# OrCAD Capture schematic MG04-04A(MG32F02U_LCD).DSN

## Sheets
1 01. Power Supply: size E; title: System Power; rev: 1.1; company: megawin; note: MG04-04
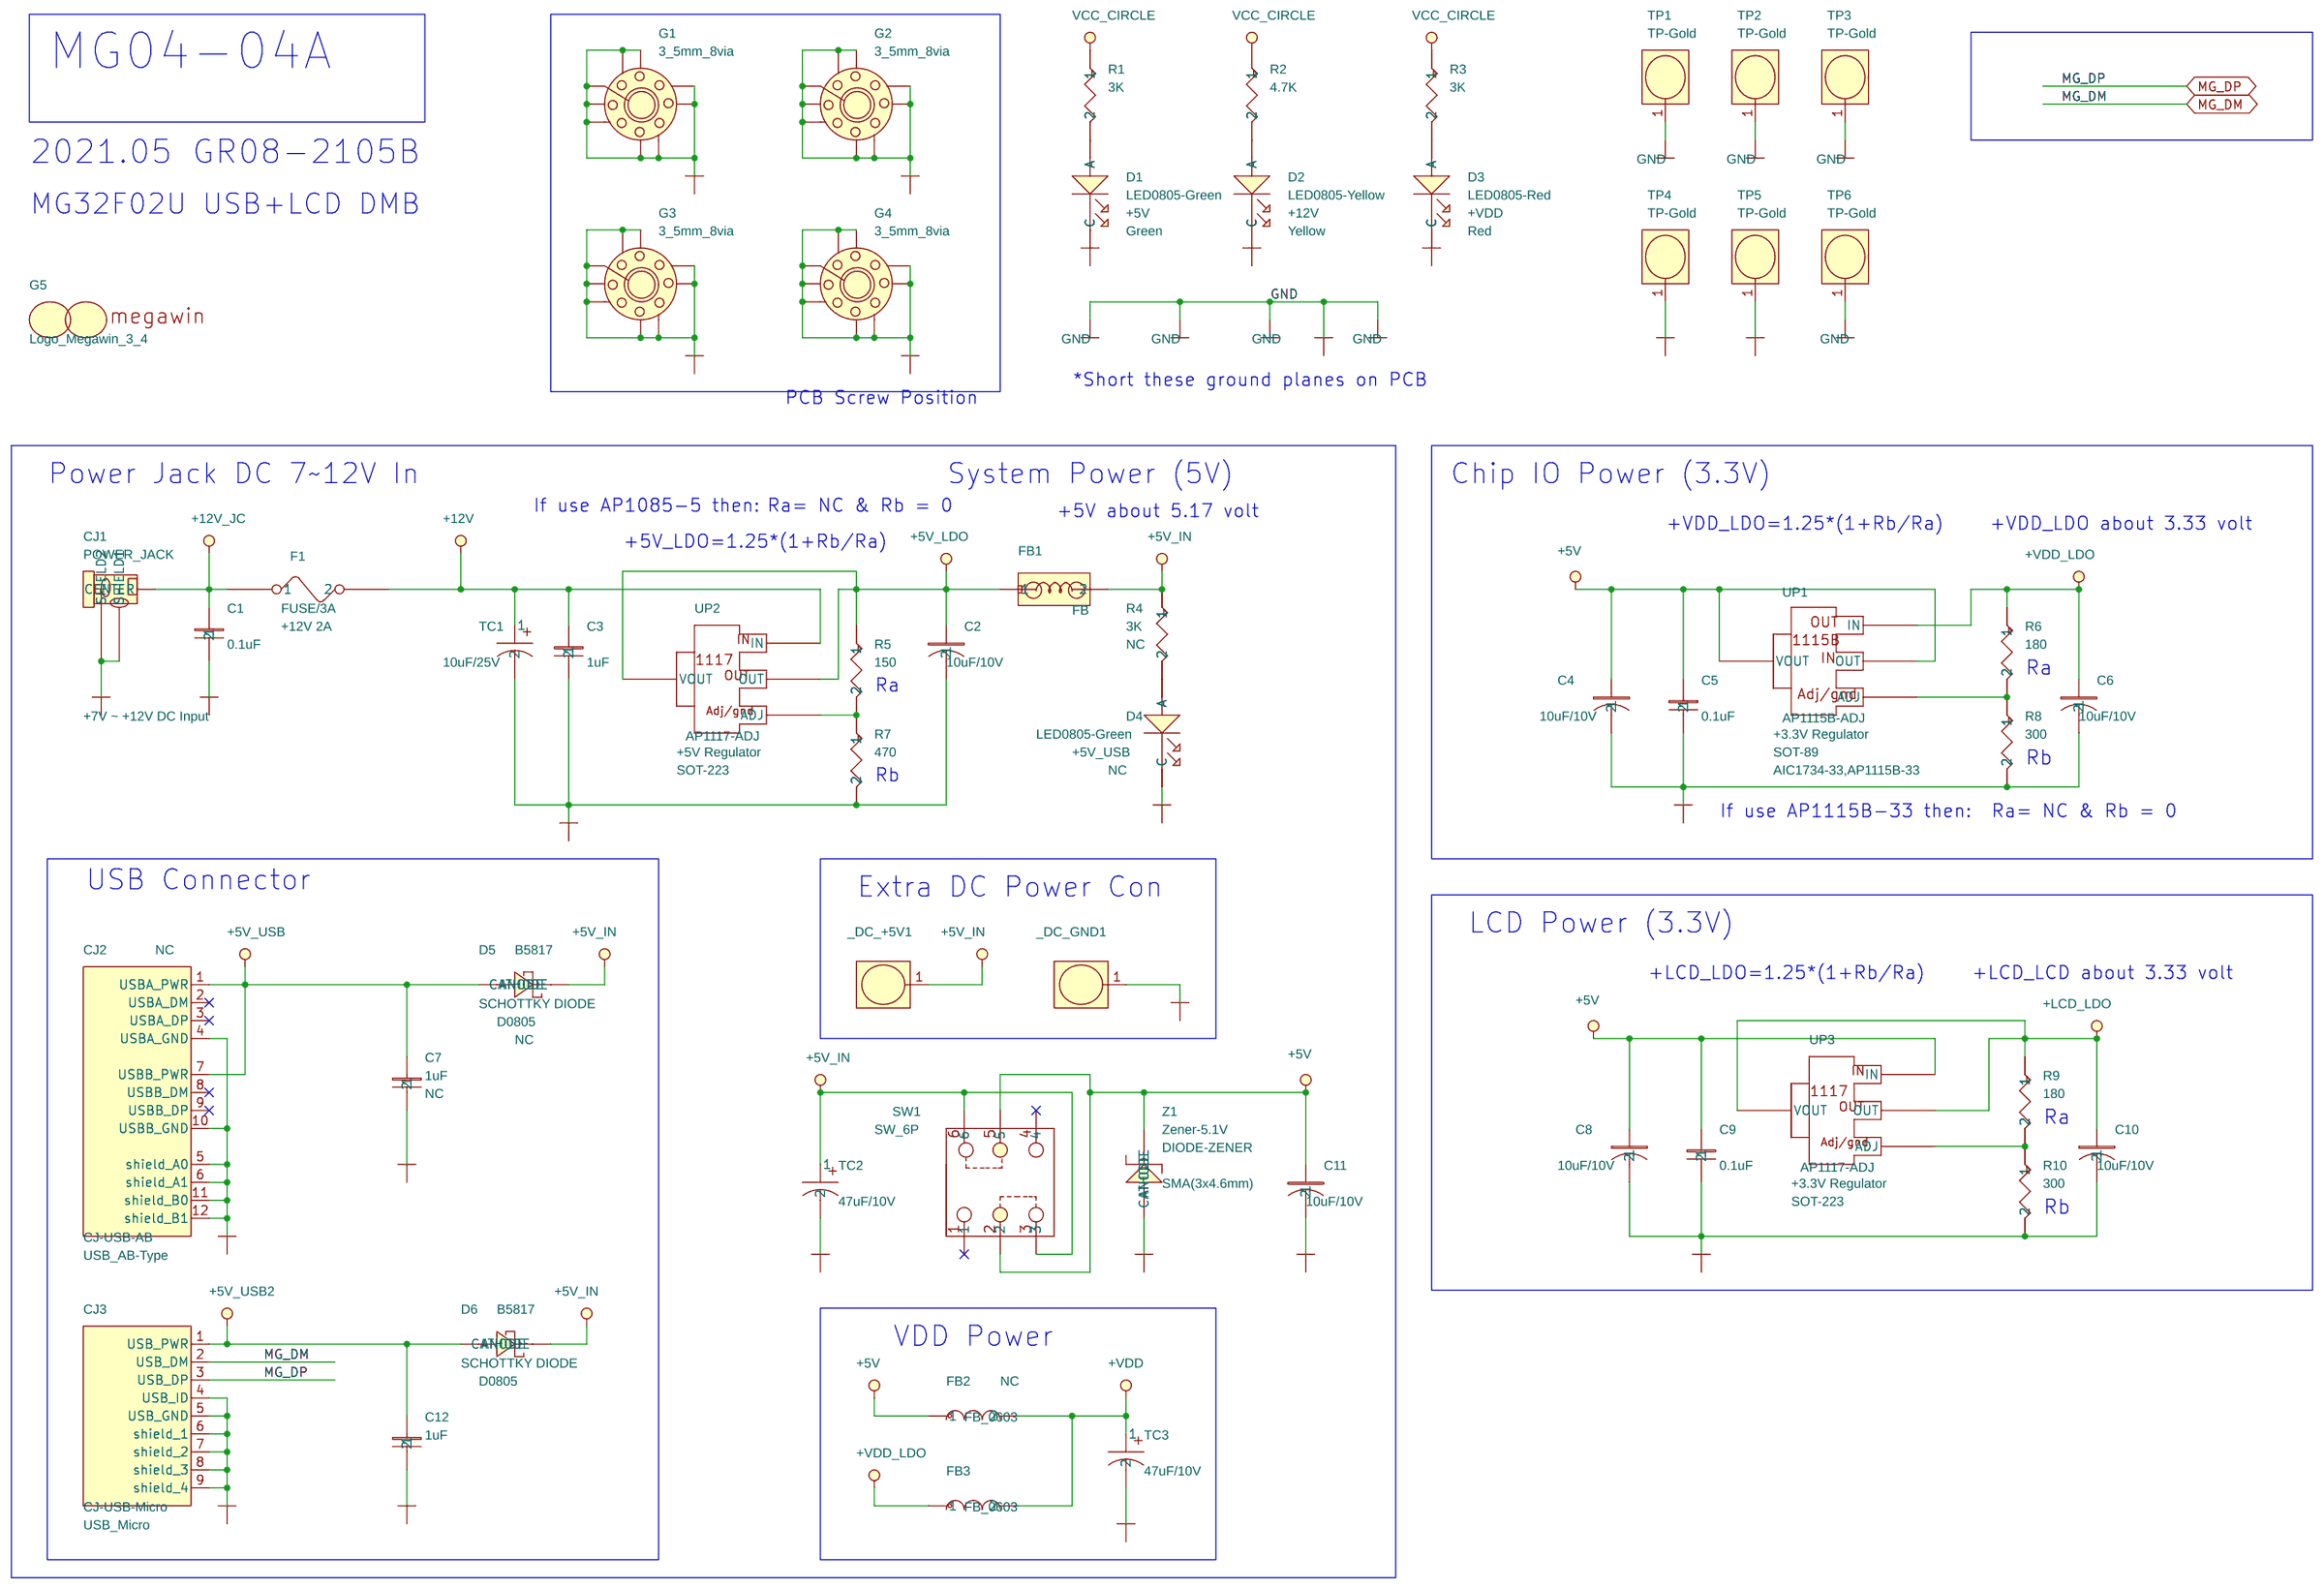
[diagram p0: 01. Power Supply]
2 02. MG32F02U_Main: size C; title: MG32F02U Chip; rev: 1.0
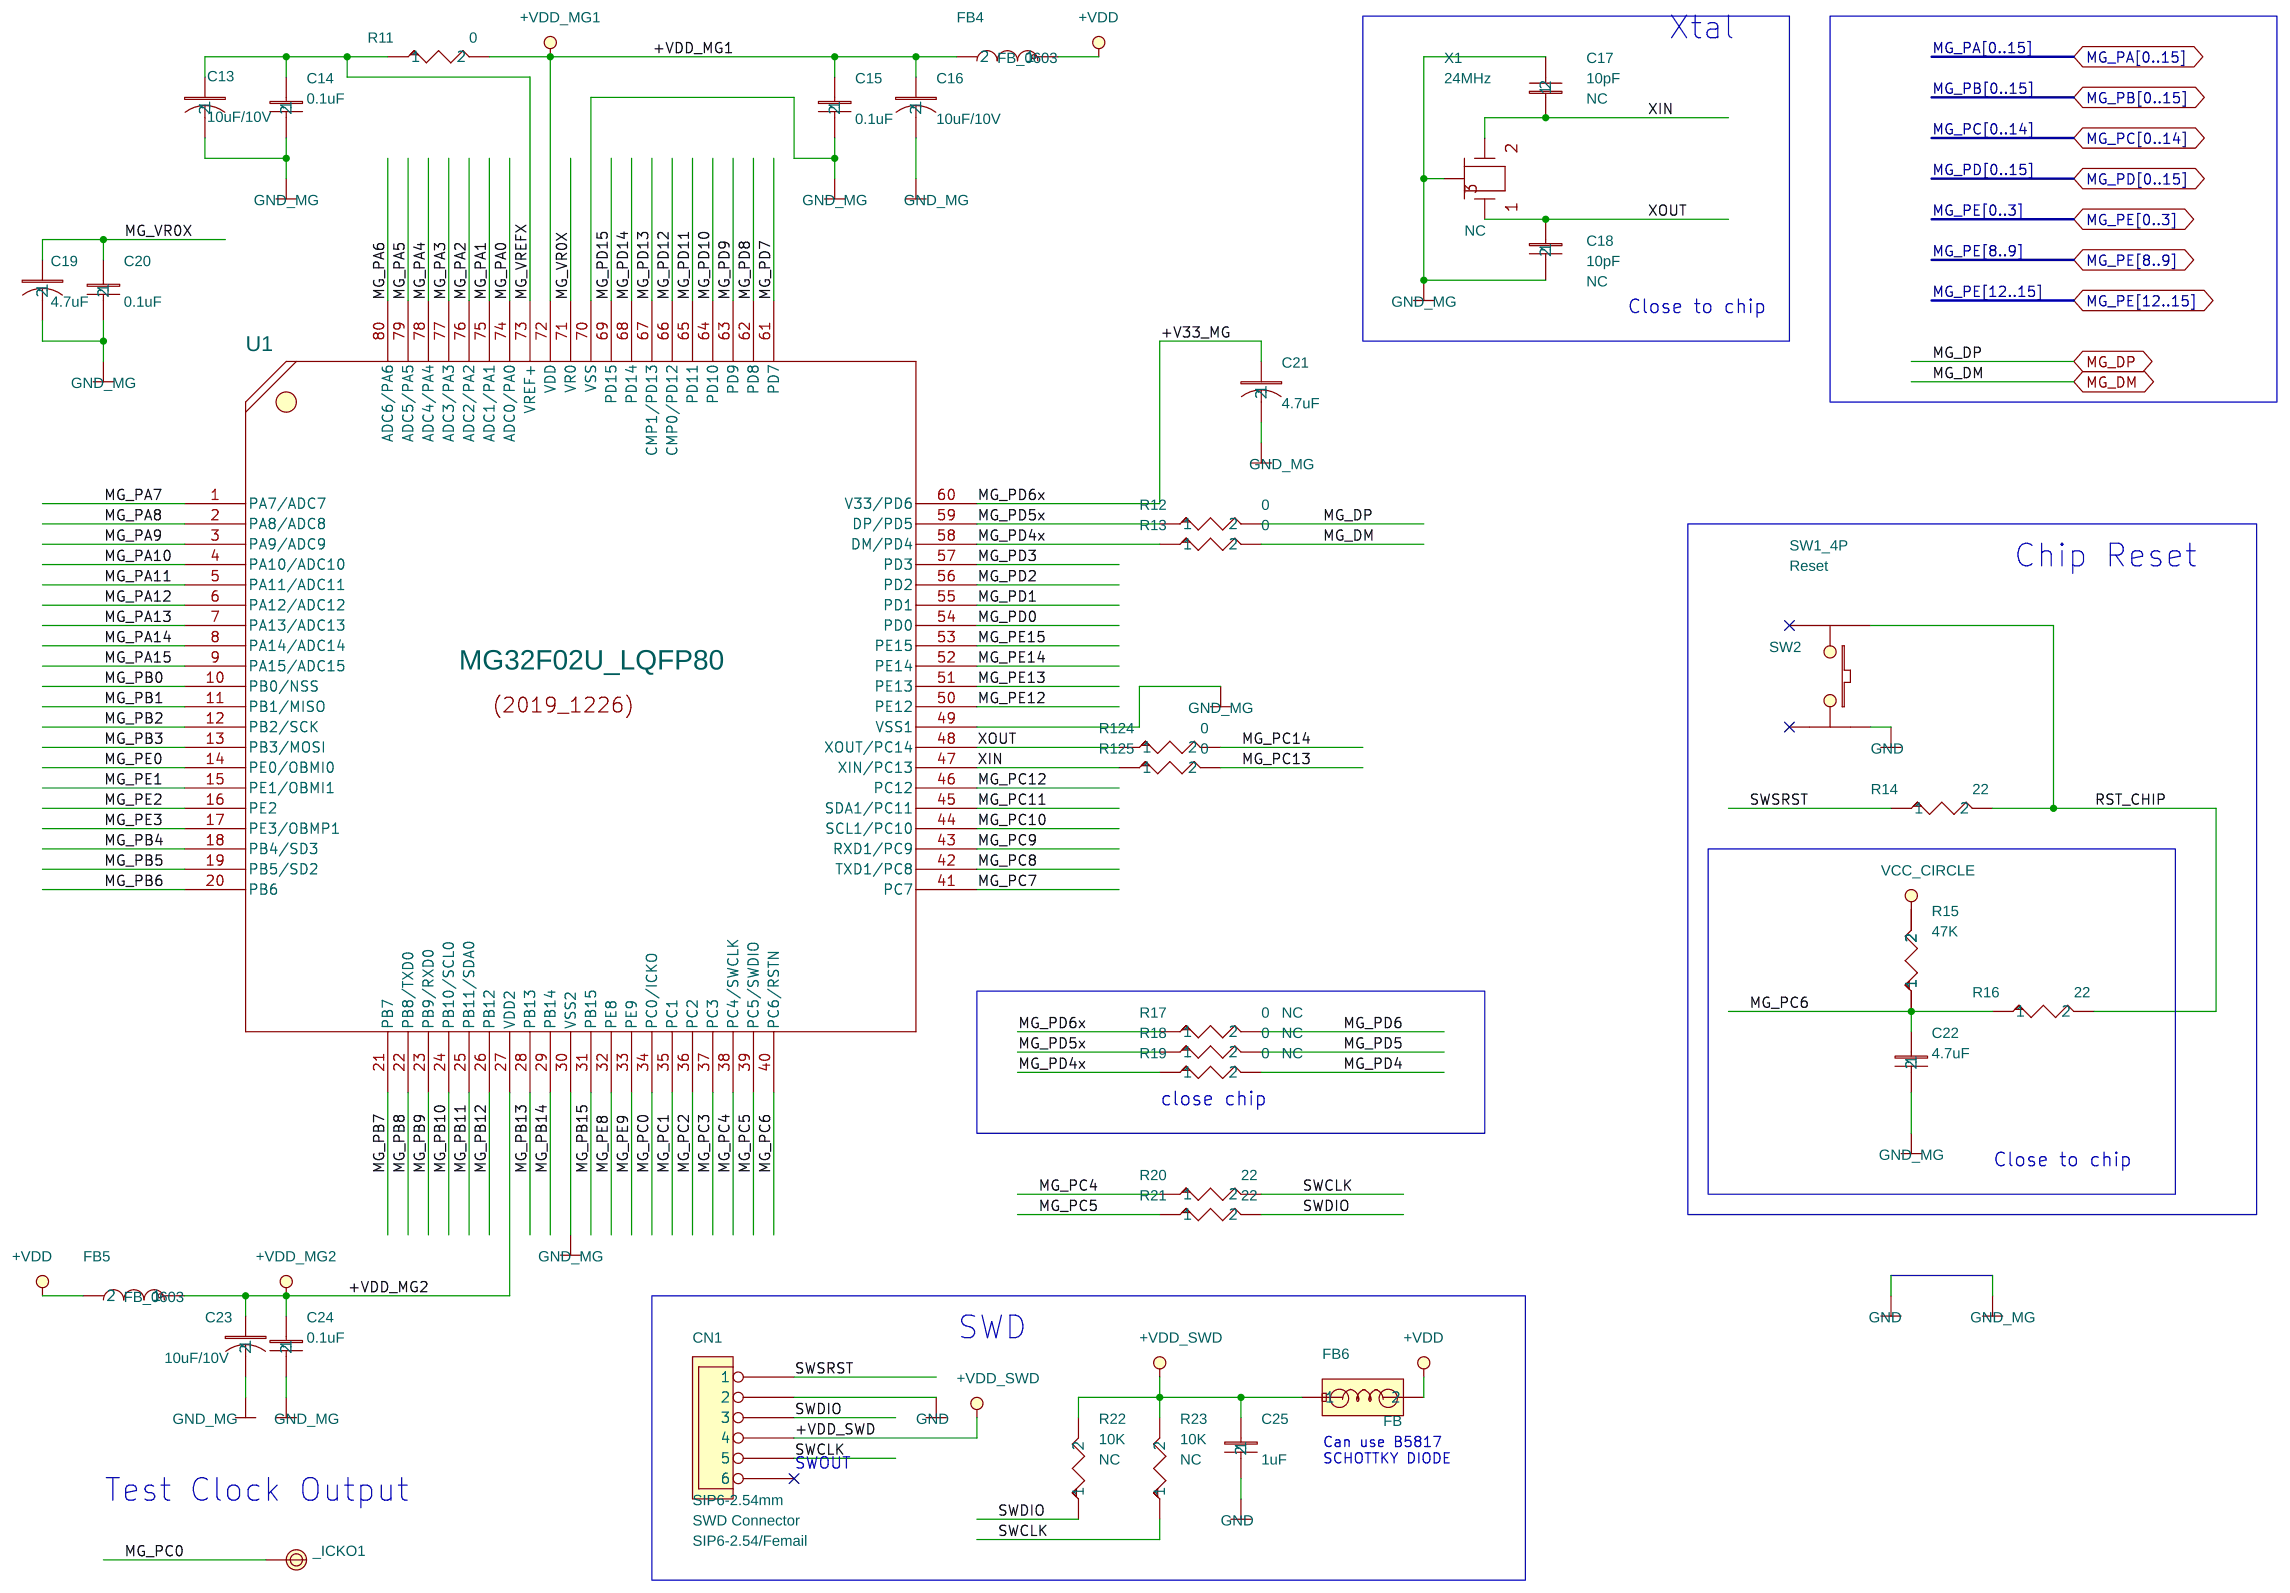
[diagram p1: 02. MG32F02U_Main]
3 03. Muti-Function IF: size C; title: Multi-Function Interface
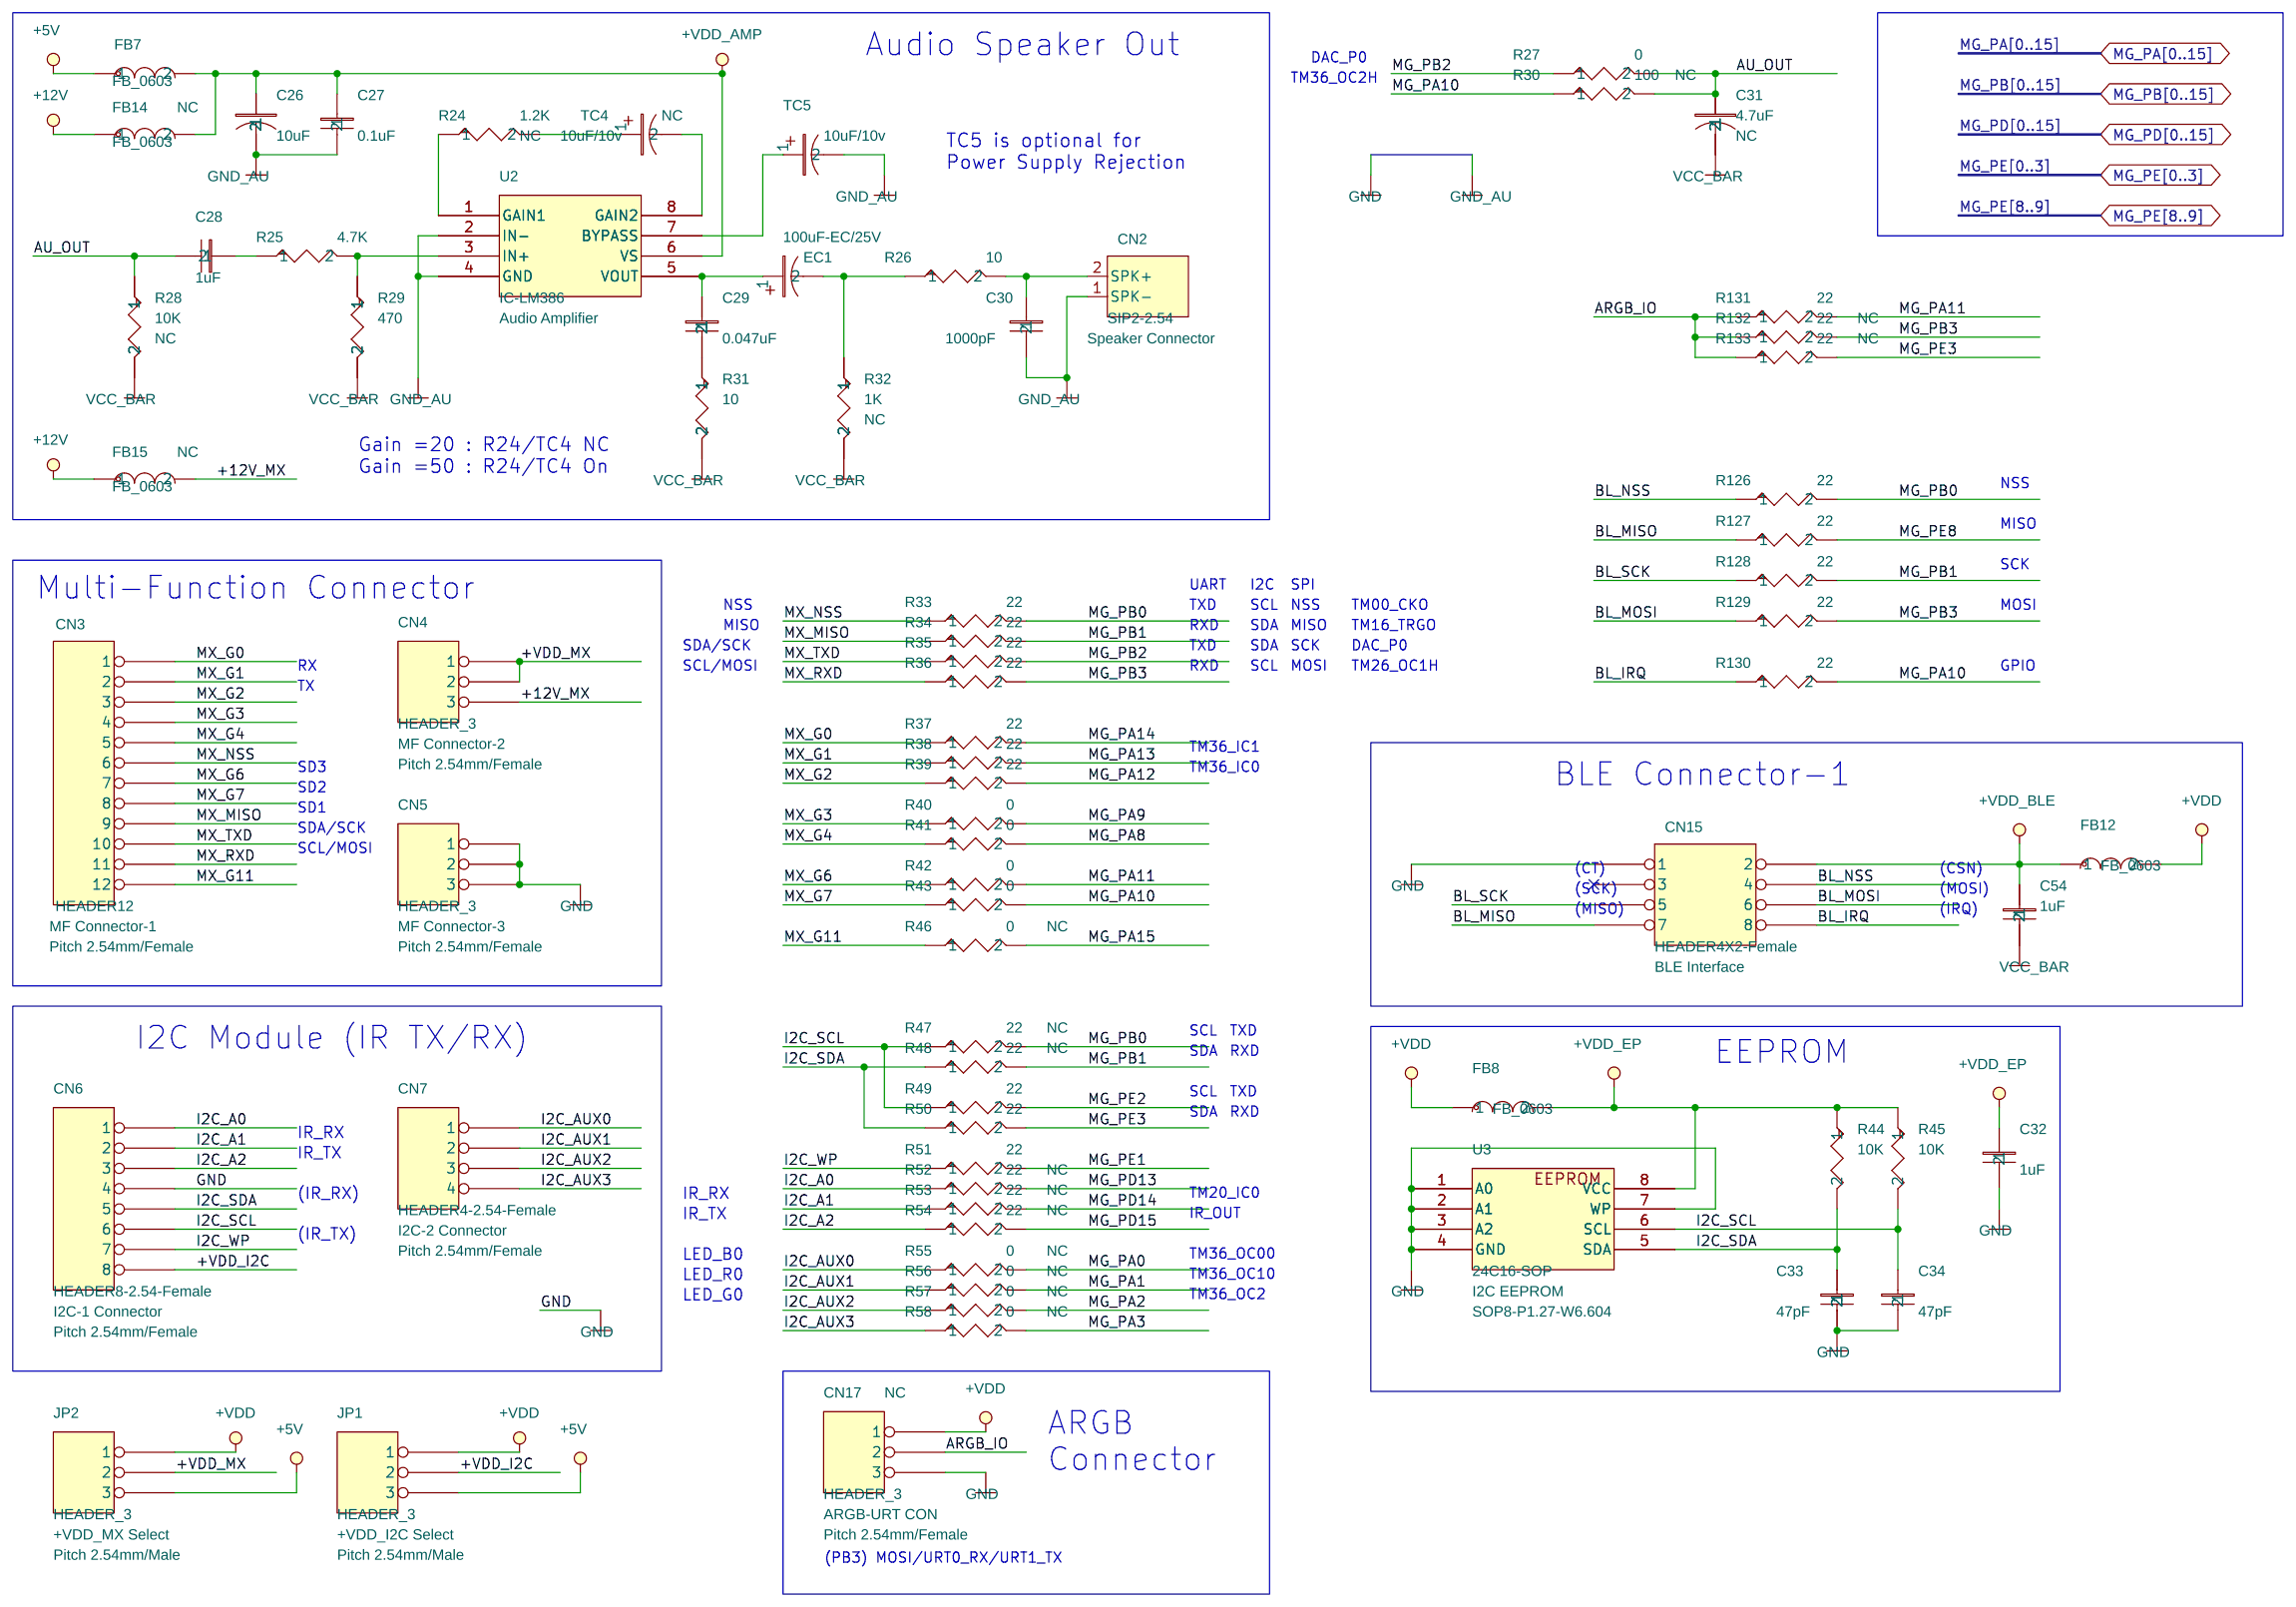
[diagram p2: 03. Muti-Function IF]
4 04. LCD IF: size C; title: LCD Interface; rev: 1.0
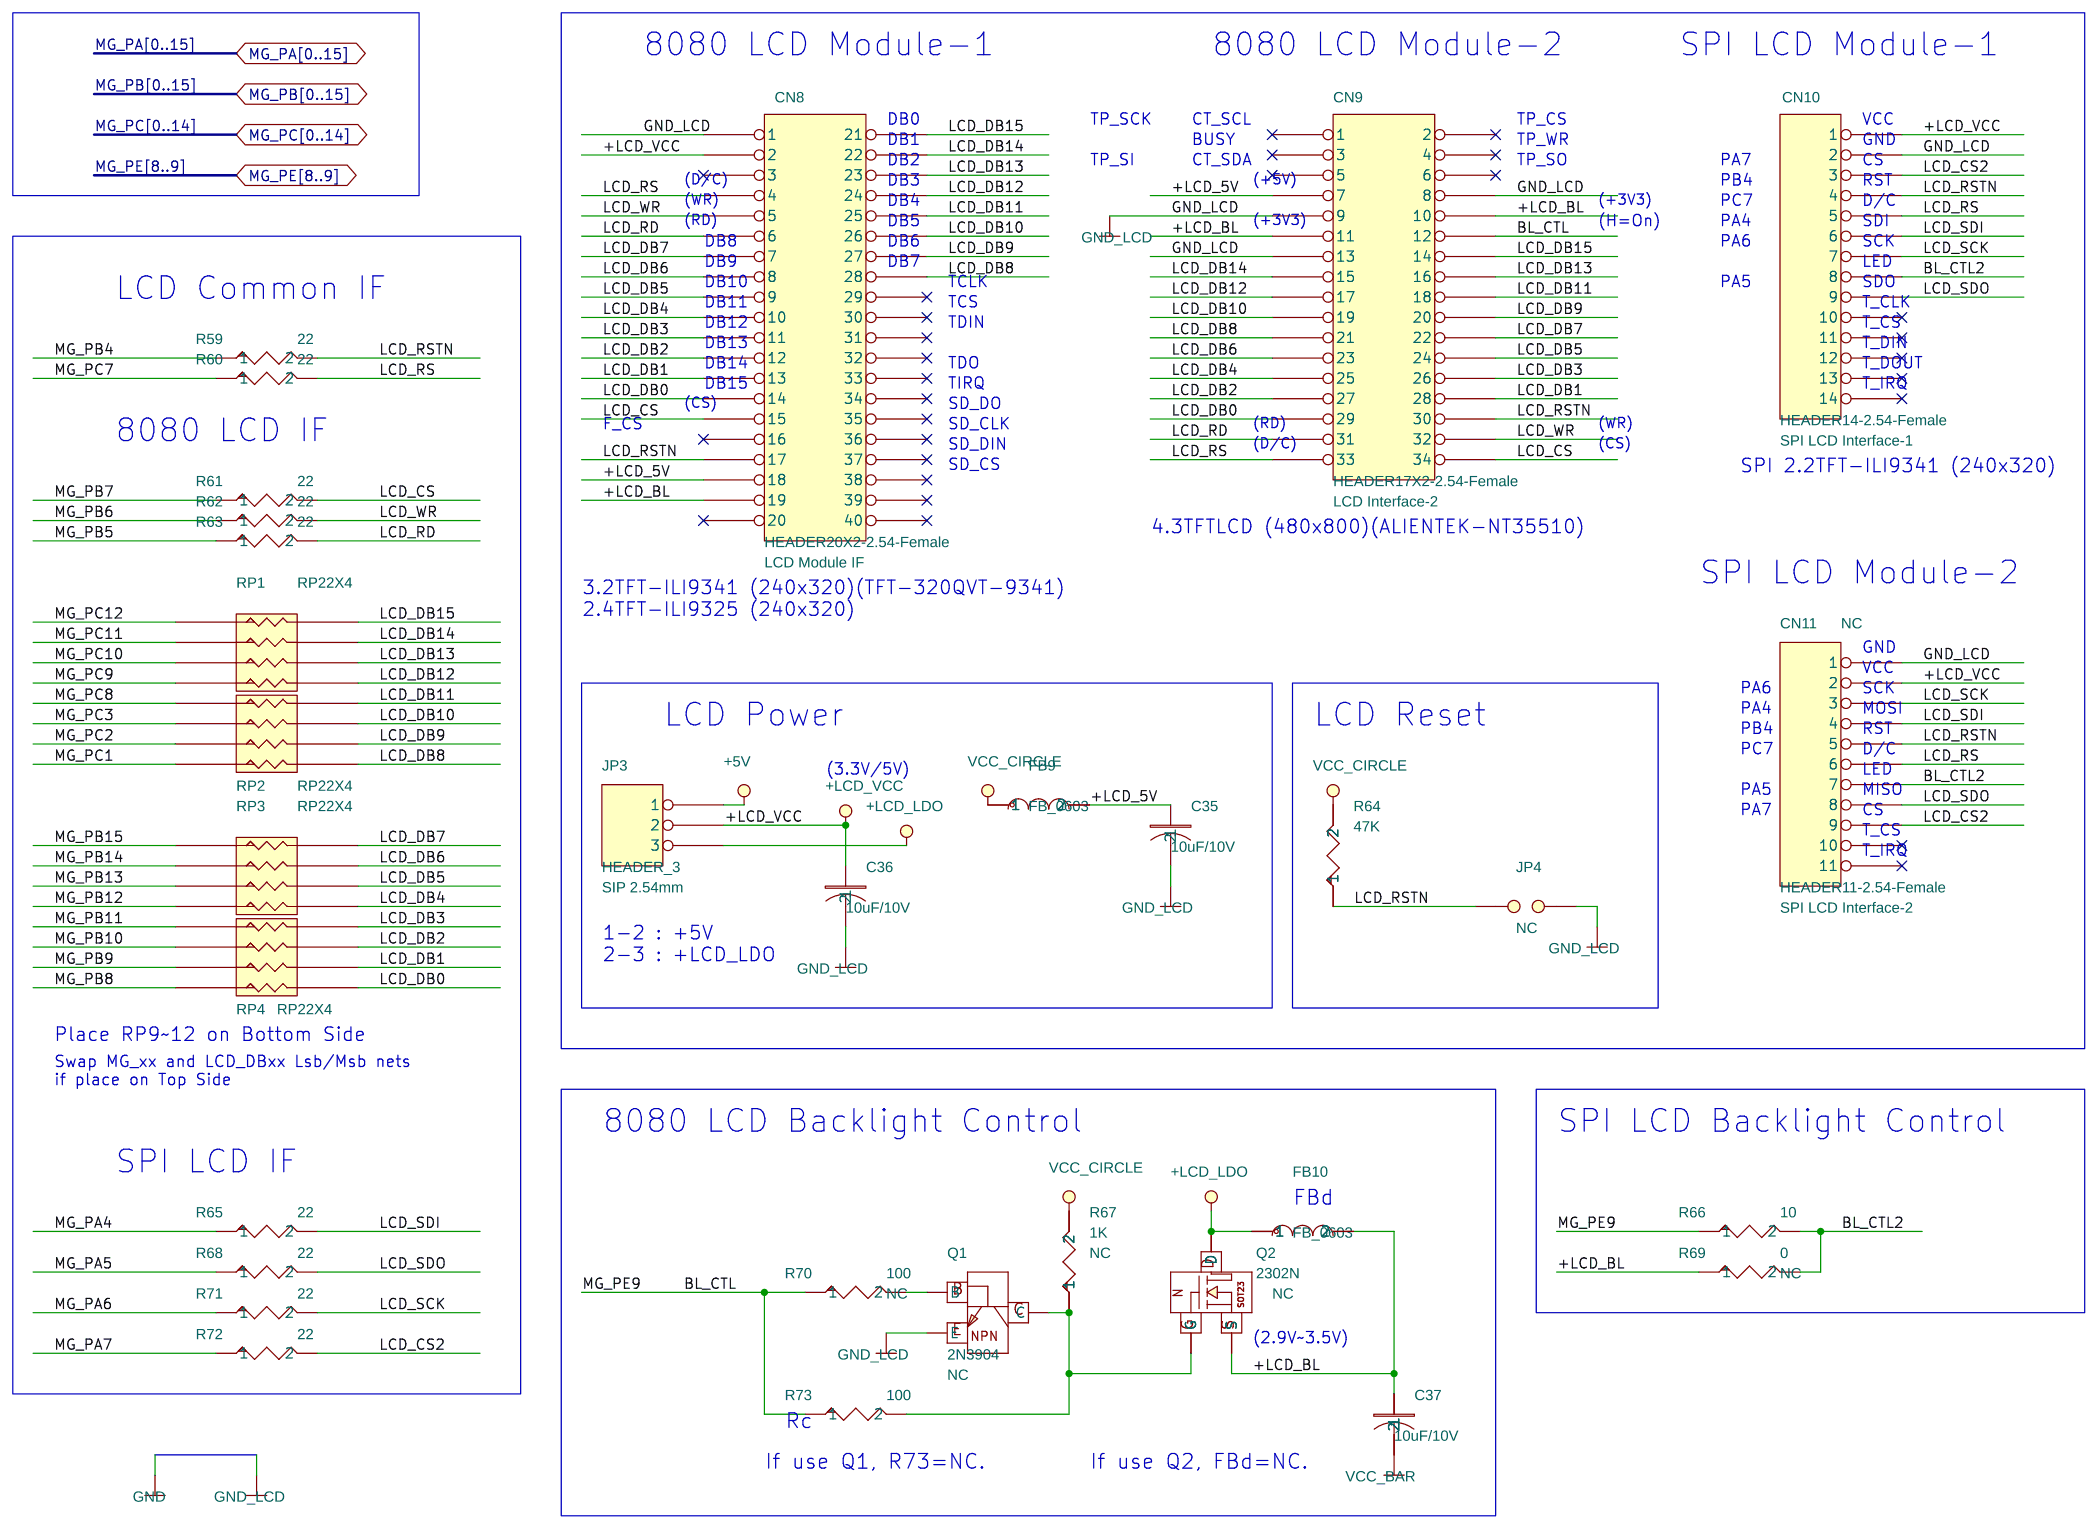
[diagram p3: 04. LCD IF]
5 05. SPI Flash and LED: size C; title: SPI Flash and LED; rev: 1.0
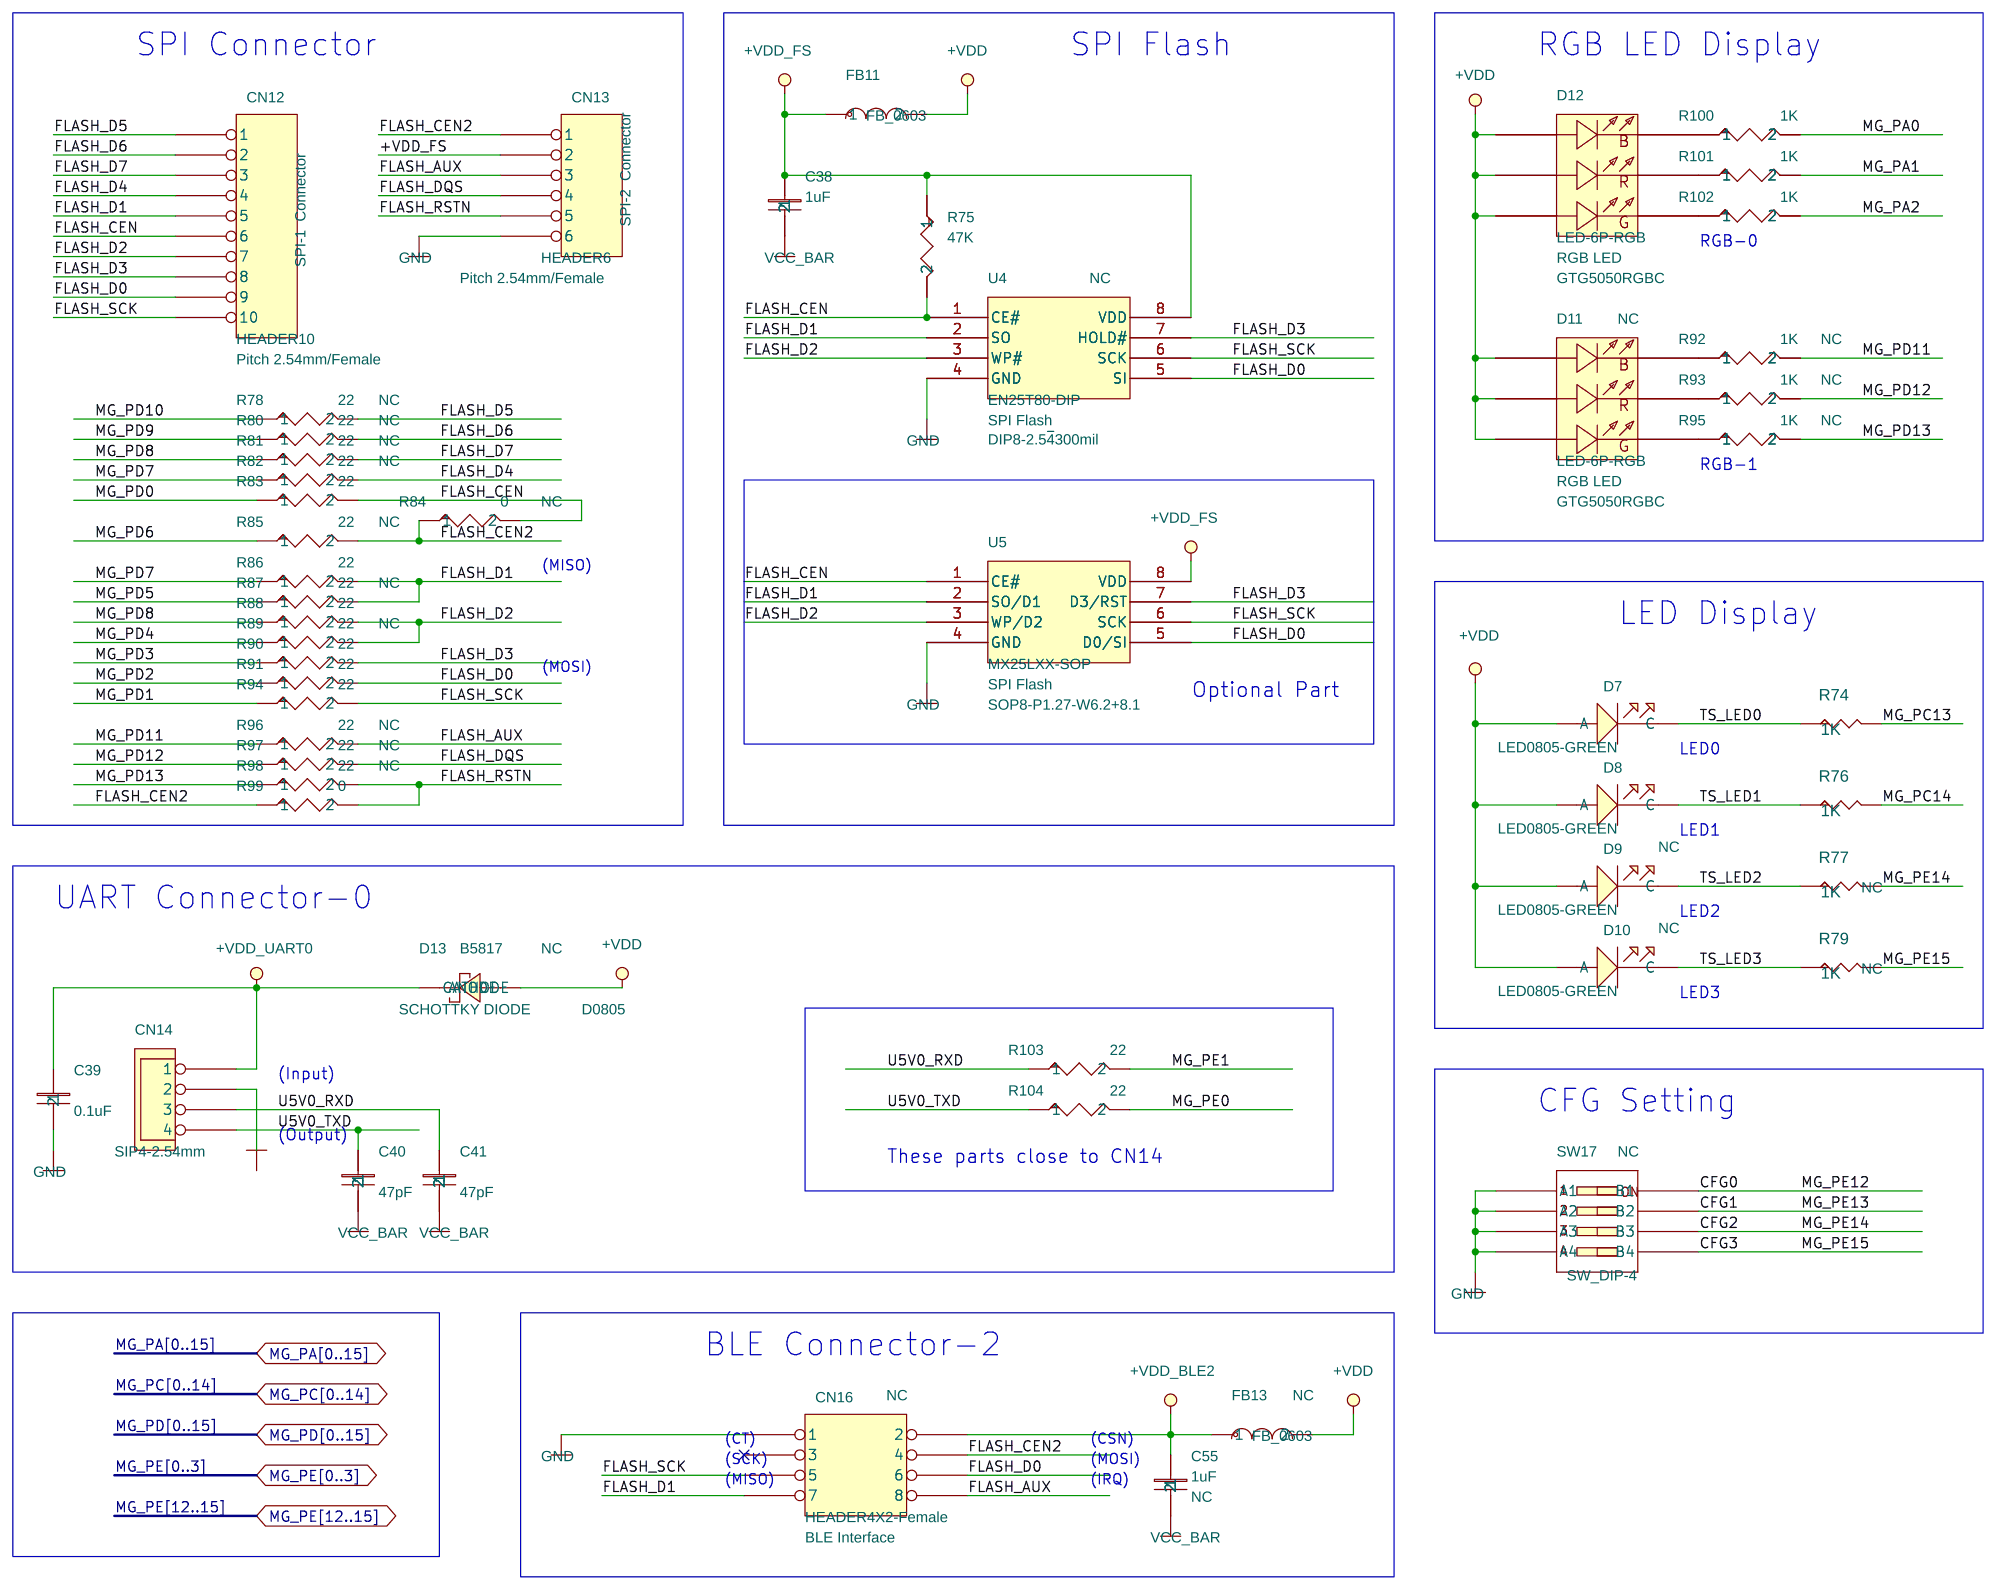
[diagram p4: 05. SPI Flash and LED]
6 06. Keys: size B; title: Keys; rev: 1.0
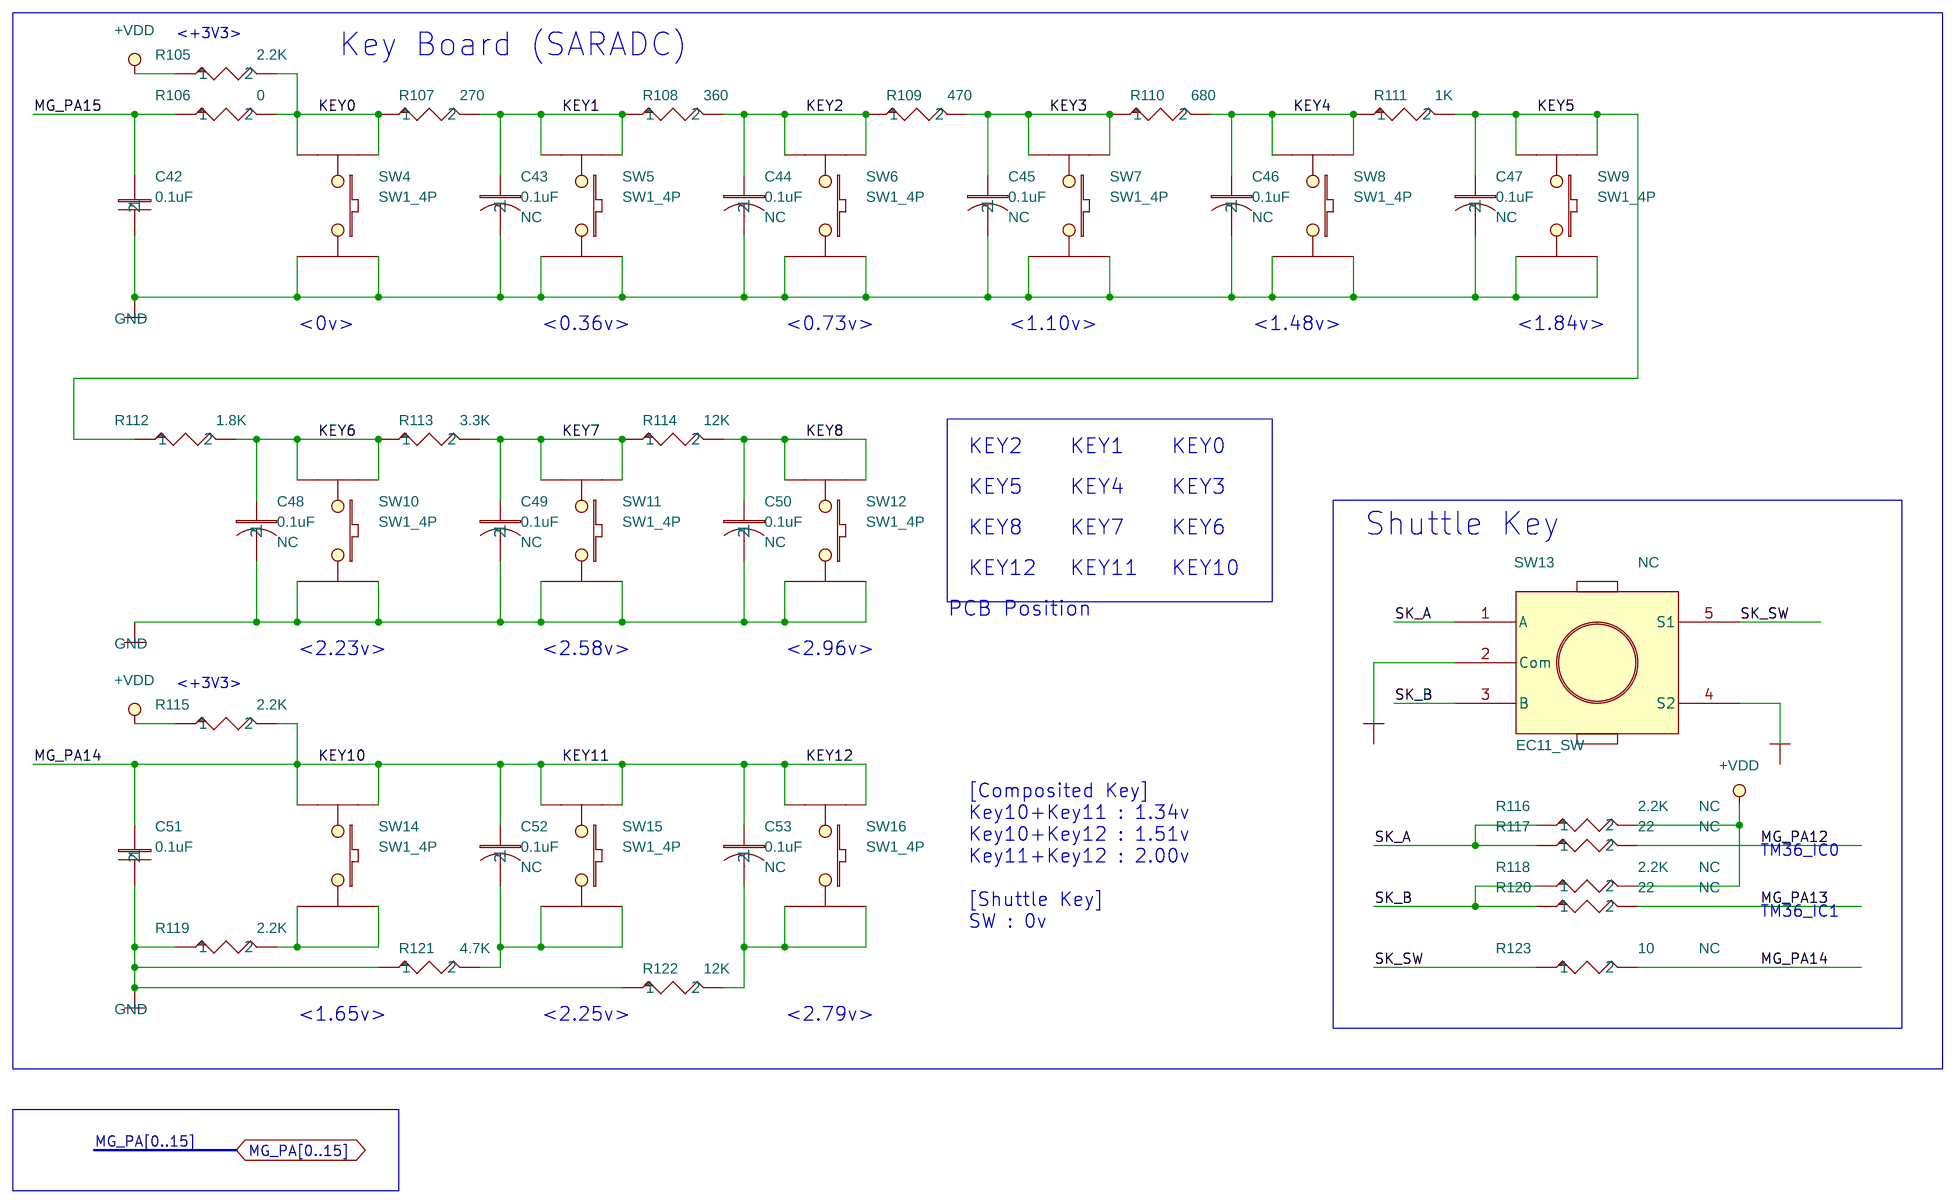
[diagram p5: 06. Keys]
7 20. Board Comment: title: Board Comment; rev: 1.0
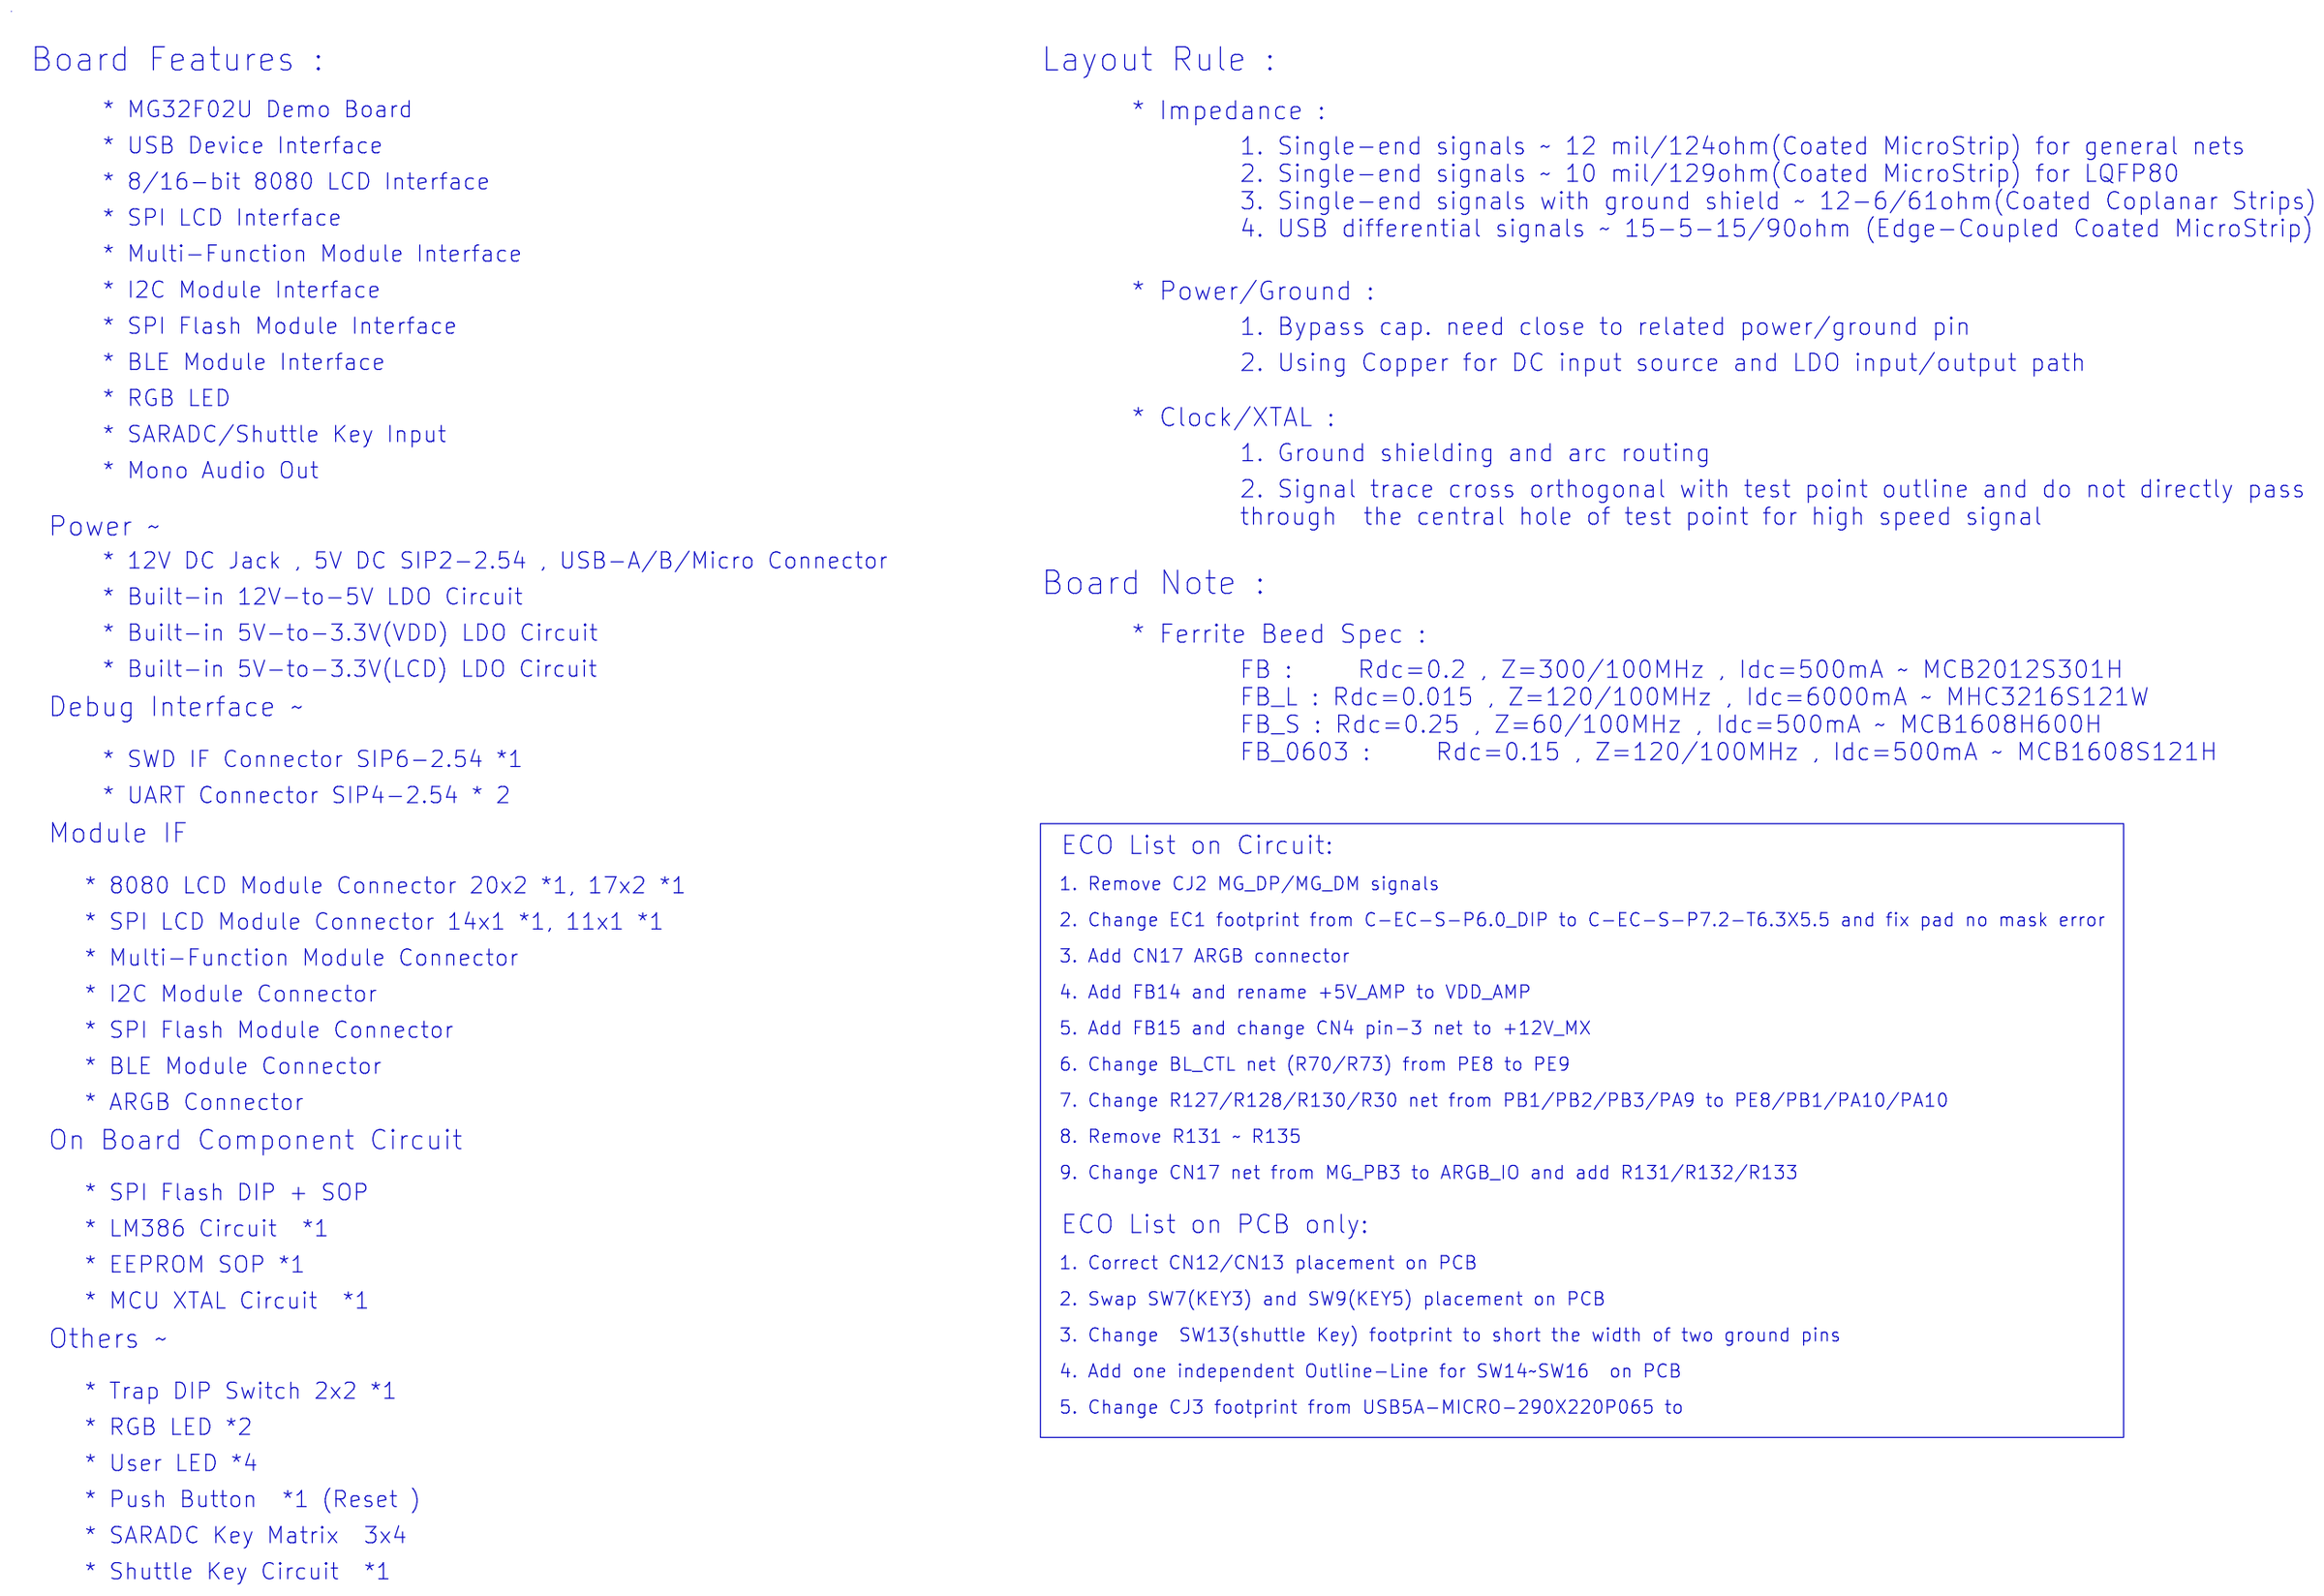
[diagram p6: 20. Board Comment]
8 21. PCB Placement: title: PCB Placement Plan; rev: 1.0
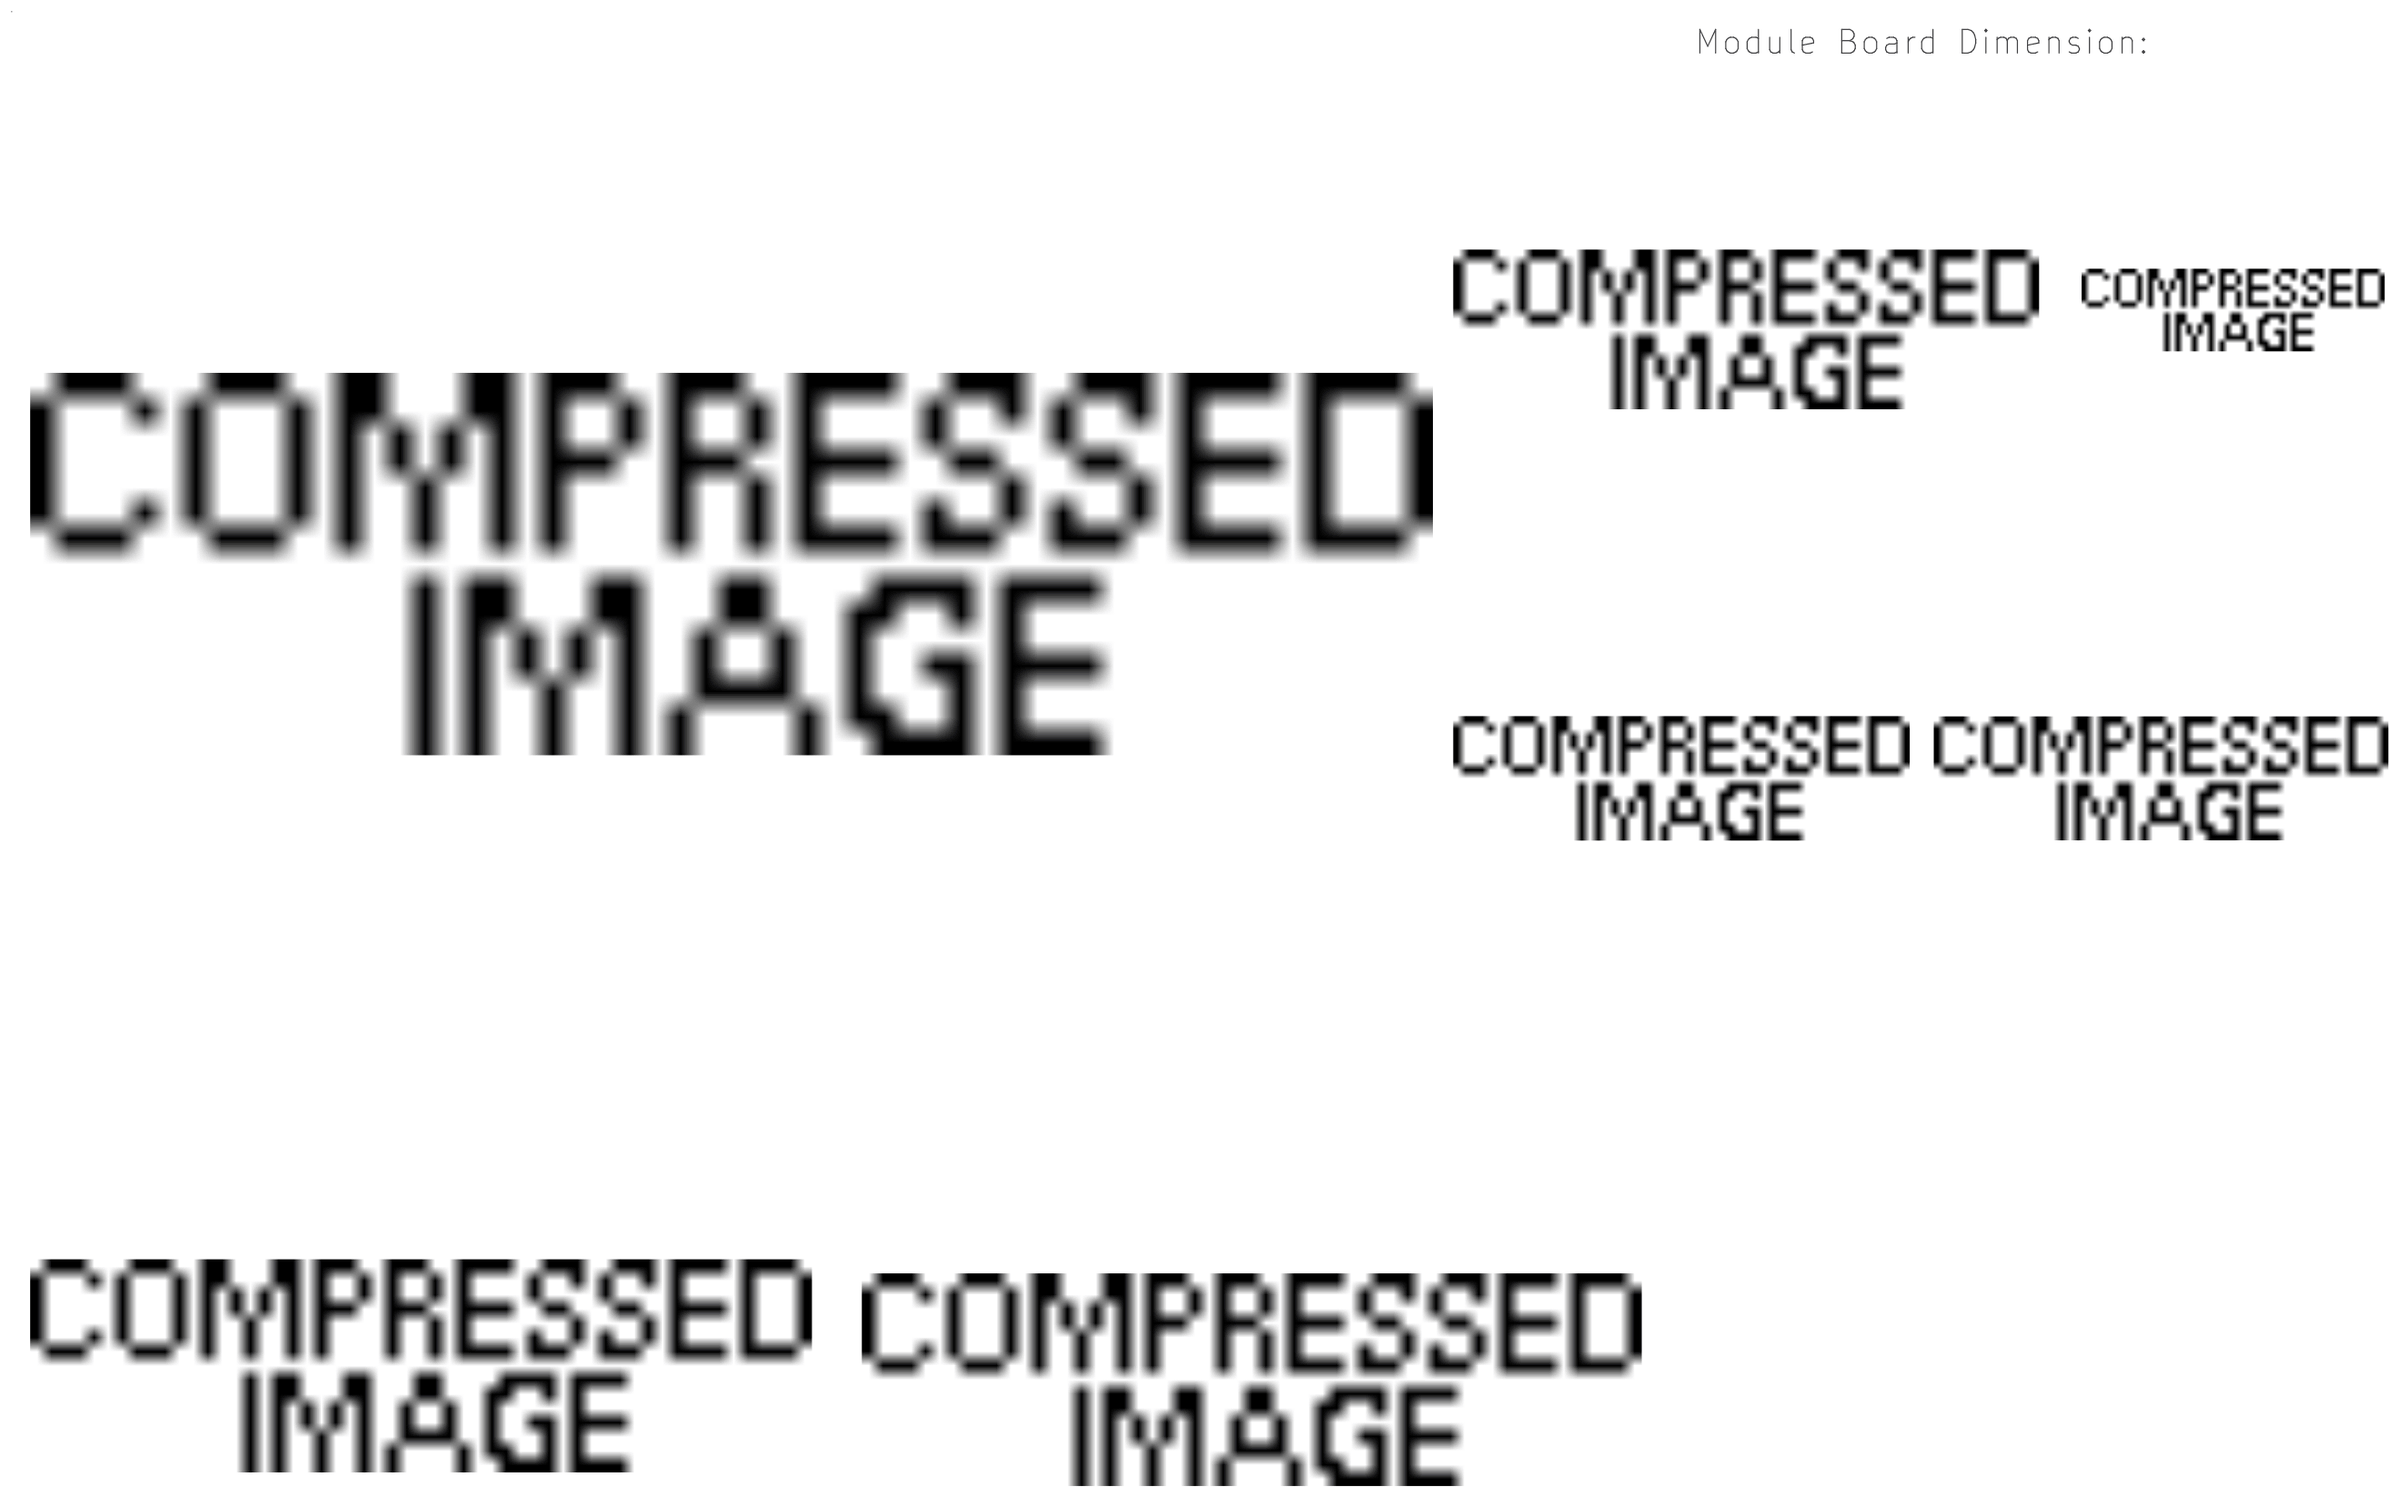
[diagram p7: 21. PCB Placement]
9 22. Power System: title: Power System; rev: 1.0
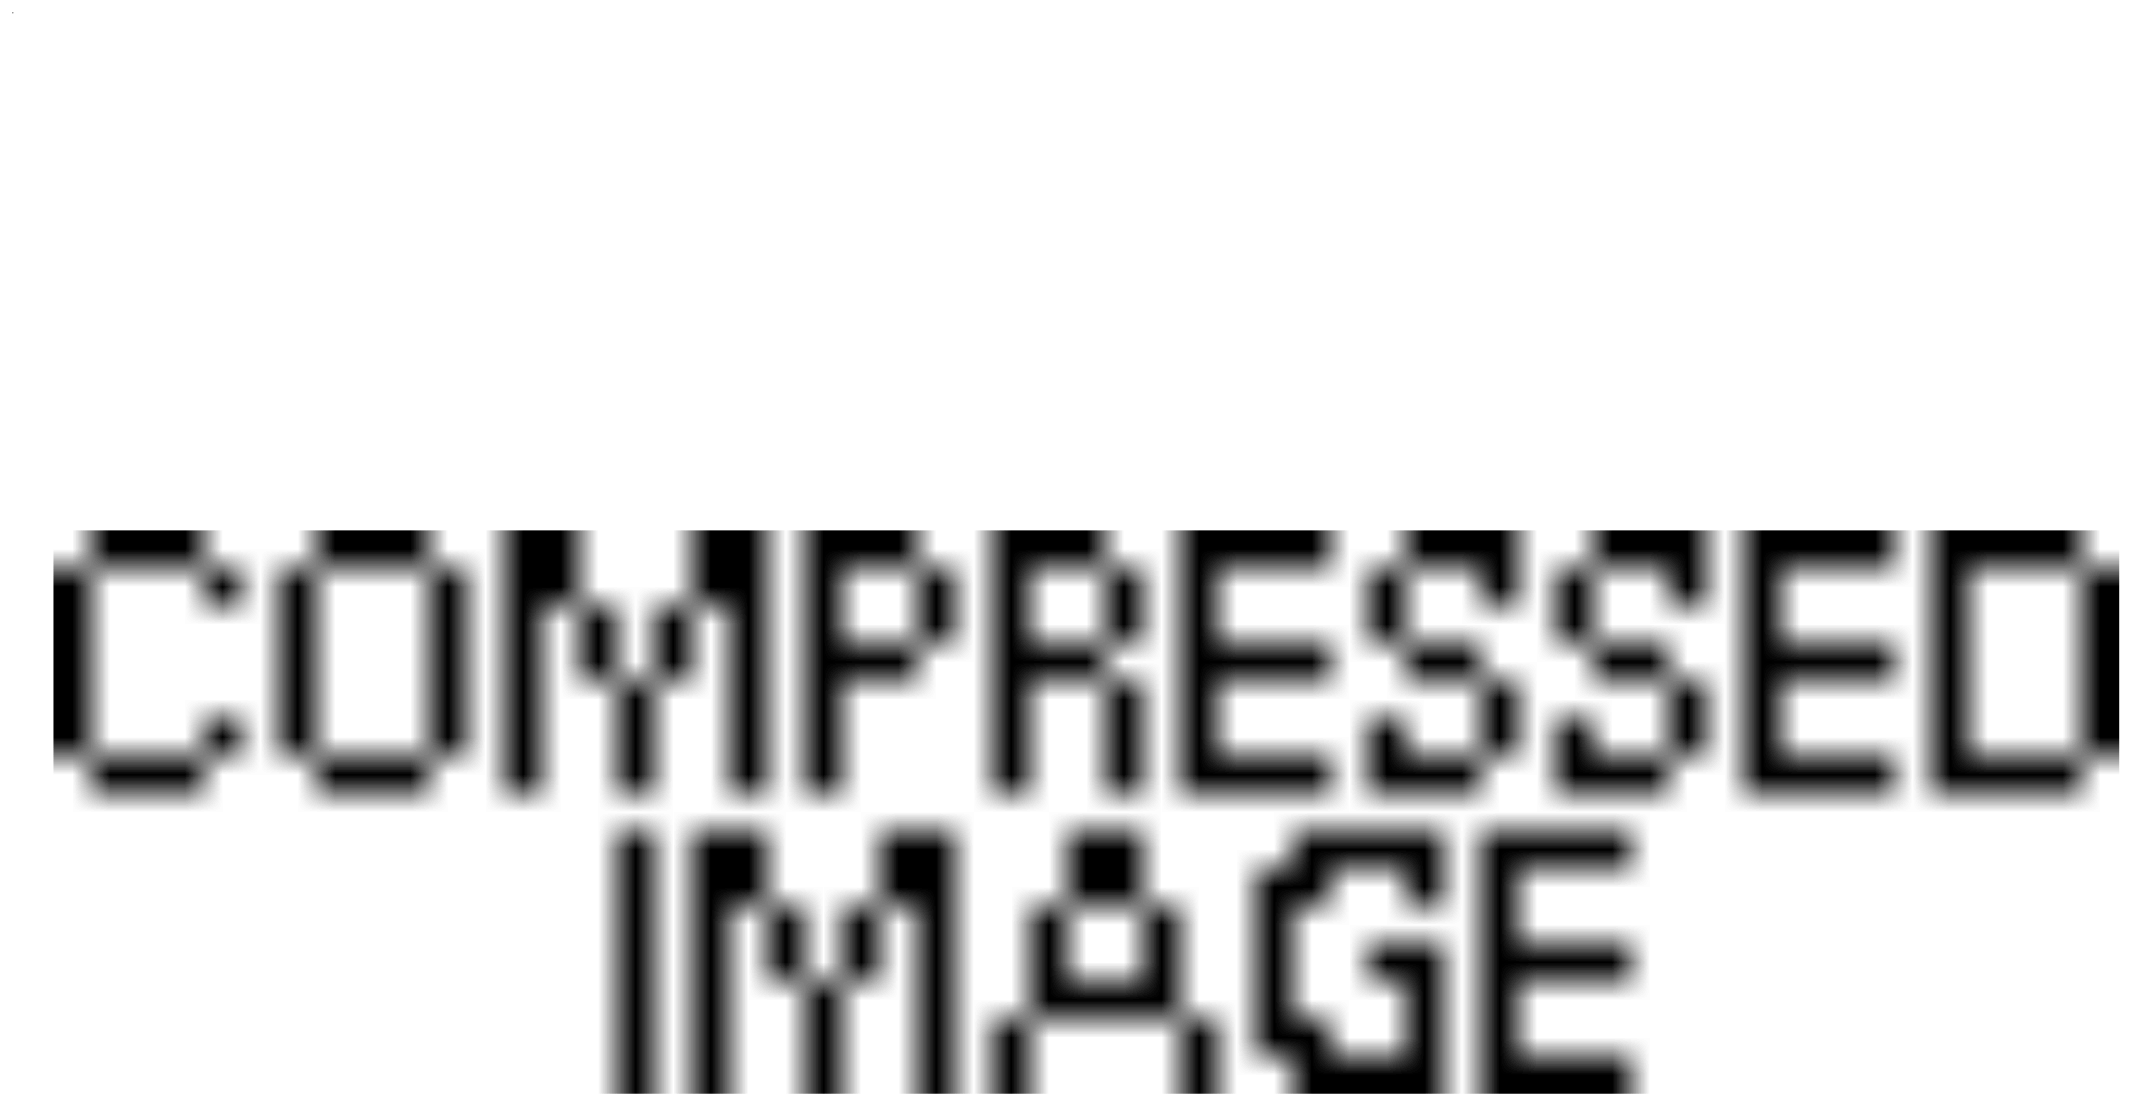
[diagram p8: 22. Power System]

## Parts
sheet 01. Power Supply
_DC_+5V1  +5V_DC  [SIP1-50]
_DC_GND1  GND  [SIP1-50]
C1  0.1uF  [C-0603]
C2  10uF/10V  [C-0805]
C3  1uF  [C-0603]
C4  10uF/10V  [C-0805]
C5  0.1uF  [C-0603]
C6  10uF/10V  [C-0805]
C7  1uF  [C-0603]
C8  10uF/10V  [C-0805]
C9  0.1uF  [C-0603]
C10  10uF/10V  [C-0805]
C11  10uF/10V  [C-0805]
C12  1uF  [C-0603]
CJ1  POWER_JACK  [JACK-DC-TC18013]
CJ2  CJ-USB-AB  [CON_USB-AB]
CJ3  CJ-USB-Micro  [USB5-MICRO-7.5.X5.4P065]
D1  LED0805-Green  [LED-0805]
D2  LED0805-Yellow  [LED-0805]
D3  LED0805-Red  [LED-0805]
D4  LED0805-Green  [LED-0805]
D5  B5817  [D-0805]
D6  B5817  [D-0805]
F1  FUSE/3A  [FUSE-1206]
FB1  FB  [L0805+DIP]
FB2  FB_0603  [L-0603]
FB3  FB_0603  [L-0603]
G1  3_5mm_8via  [SCREW9-H3.5-R8]
G2  3_5mm_8via  [SCREW9-H3.5-R8]
G3  3_5mm_8via  [SCREW9-H3.5-R8]
G4  3_5mm_8via  [SCREW9-H3.5-R8]
G5  Logo_Megawin_3_4  [MEGAWIN_3.4]
R1  3K  [R-0603]
R2  4.7K  [R-0603]
R3  3K  [R-0603]
R4  3K  [R-0603]
R5  150  [R-0603]
R6  180  [R-0603]
R7  470  [R-0603]
R8  300  [R-0603]
R9  180  [R-0603]
R10  300  [R-0603]
SW1  SW_6P  [SW6-P2.54-Z8X8X12.5]
TC1  10uF/25V  [C-1812+]
TC2  47uF/10V  [C-1210+]
TC3  47uF/10V  [C-1210+]
TP1  TP-Gold  [SIP1-39]
TP2  TP-Gold  [SIP1-39]
TP3  TP-Gold  [SIP1-39]
TP4  TP-Gold  [SIP1-39]
TP5  TP-Gold  [SIP1-39]
TP6  TP-Gold  [SIP1-39]
UP1  AP1115B-ADJ  [SOT-89-1]
UP2  AP1117-ADJ  [SOT223H\3P]
UP3  AP1117-ADJ  [SOT223H\3P]
Z1  Zener-5.1V  [D-5819-1]
sheet 02. MG32F02U_Main
_ICKO1  TP-COIL  [TPH60-COIL]
C13  10uF/10V  [C-0805]
C14  0.1uF  [C-0603]
C15  0.1uF  [C-0603]
C16  10uF/10V  [C-0805]
C17  10pF  [C-0603]
C18  10pF  [C-0603]
C19  4.7uF  [C-0805]
C20  0.1uF  [C-0603]
C21  4.7uF  [C-0805]
C22  4.7uF  [C-0603]
C23  10uF/10V  [C-0805]
C24  0.1uF  [C-0603]
C25  1uF  [C-0603]
CN1  SIP6-2.54mm  [HD6-P2.54-UL]
FB4  FB_0603  [L-0603]
FB5  FB_0603  [L-0603]
FB6  FB  [L0805+DIP]
R11  0  [R-0603]
R12  0  [R-0603]
R13  0  [R-0603]
R14  22  [R-0603]
R15  47K  [R-0603]
R16  22  [R-0603]
R17  0  [R-0603]
R18  0  [R-0603]
R19  0  [R-0603]
R20  22  [R-0603]
R21  22  [R-0603]
R22  10K  [R-0603]
R23  10K  [R-0603]
R124  0  [R-0603]
R125  0  [R-0603]
SW2  SW1_4P  [SW-TACT-P4.5X6.5-Z6.2X6.2X5]
U1  MG32F02U_LQFP80  [QFP80-P0.4-Z12X12]
X1  24MHz  [XTAL-HC49US-G2]
sheet 03. Muti-Function IF
C26  10uF  [C-0805]
C27  0.1uF  [C-0603]
C28  1uF  [C-0603]
C29  0.047uF  [C-0603]
C30  1000pF  [C0603]
C31  4.7uF  [C-0805]
C32  1uF  [C-0603]
C33  47pF  [C-0603]
C34  47pF  [C-0603]
C54  1uF  [C-0603]
CN2  SIP2-2.54  [SIP2-2.54]
CN3  HEADER12  [SIP12-P2.54]
CN4  HEADER_3  [SIP3-P2.54]
CN5  HEADER_3  [SIP3-P2.54]
CN6  HEADER8-2.54-Female  [SIP8-P2.54]
CN7  HEADER4-2.54-Female  [SIP4-P2.54]
CN15  HEADER4X2-Female  [HD4X2-P2.54]
CN17  HEADER_3  [SIP3-P2.54]
EC1  100uF-EC/25V  [C-EC-S-P7.2-T6.3X5.5]
FB7  FB_0603  [L-0603]
FB8  FB_0603  [L-0603]
FB12  FB_0603  [L-0603]
FB14  FB_0603  [L-0603]
FB15  FB_0603  [L-0603]
JP1  HEADER_3  [SIP3-P2.54]
JP2  HEADER_3  [SIP3-P2.54]
R24  1.2K  [R-0603]
R25  4.7K  [R-0603]
R26  10  [R-0603]
R27  0  [R-0603]
R28  10K  [R-0603]
R29  470  [R-0603]
R30  100  [R-0603]
R31  10  [R-0603]
R32  1K  [R-0603]
R33  22  [R-0603]
R34  22  [R-0603]
R35  22  [R-0603]
R36  22  [R-0603]
R37  22  [R-0603]
R38  22  [R-0603]
R39  22  [R-0603]
R40  0  [R-0603]
R41  0  [R-0603]
R42  0  [R-0603]
R43  0  [R-0603]
R44  10K  [R-0603]
R45  10K  [R-0603]
R46  0  [R-0603]
R47  22  [R-0603]
R48  22  [R-0603]
R49  22  [R-0603]
R50  22  [R-0603]
R51  22  [R-0603]
R52  22  [R-0603]
R53  22  [R-0603]
R54  22  [R-0603]
R55  0  [R-0603]
R56  0  [R-0603]
R57  0  [R-0603]
R58  0  [R-0603]
R126  22  [R-0603]
R127  22  [R-0603]
R128  22  [R-0603]
R129  22  [R-0603]
R130  22  [R-0603]
R131  22  [R-0603]
R132  22  [R-0603]
R133  22  [R-0603]
TC4  10uF/10v  [C-1210+]
TC5  10uF/10v  [C-1210+]
U2  IC-LM386  [SOP8-P1.27-W6.2]
U3  24C16-SOP  [SOP8-P1.27-W6.604]
sheet 04. LCD IF
C35  10uF/10V  [C-0805]
C36  10uF/10V  [C-0805]
C37  10uF/10V  [C-0805]
CN8  HEADER20X2-2.54-Female  [HD20X2A-P2.54]
CN9  HEADER17X2-2.54-Female  [HD17X2-P2.54]
CN10  HEADER14-2.54-Female  [SIP14-P2.54-SPI_LCD]
CN11  HEADER11-2.54-Female  [SIP11-P2.54-SPI_LCD]
FB9  FB_0603  [L-0603]
FB10  FB_0603  [L-0603]
JP3  HEADER_3  [SIP3-P2.54]
JP4  JUMPER  [SIP2-P2.54-JUMPER]
Q1  2N3904  [SOT-23]
Q2  2302N  [SOT-23]
R59  22  [R-0603]
R60  22  [R-0603]
R61  22  [R-0603]
R62  22  [R-0603]
R63  22  [R-0603]
R64  47K  [R-0603]
R65  22  [R-0603]
R66  10  [R-0603]
R67  1K  [R-0603]
R68  22  [R-0603]
R69  0  [R-0603]
R70  100  [R-0603]
R71  22  [R-0603]
R72  22  [R-0603]
R73  100  [R-0603]
RP1  RP22X4  [RP-0603]
RP2  RP22X4  [RP-0603]
RP3  RP22X4  [RP-0603]
RP4  RP22X4  [RP-0603]
sheet 05. SPI Flash and LED
C38  1uF  [C-0603]
C39  0.1uF  [C-0603]
C40  47pF  [C-0603]
C41  47pF  [C-0603]
C55  1uF  [C-0603]
CN12  HEADER10  [SIP10-P2.54]
CN13  HEADER6  [SIP6-P2.54]
CN14  SIP4-2.54mm  [HD4-P2.54-Z12.4X5.7X7-UL]
CN16  HEADER4X2-Female  [HD4X2-P2.54]
D7  LED0805-GREEN  [LED-0805]
D8  LED0805-GREEN  [LED-0805]
D9  LED0805-GREEN  [LED-0805]
D10  LED0805-GREEN  [LED-0805]
D11  LED-6P-RGB  [LED-6P-RGB-50X50]
D12  LED-6P-RGB  [LED-6P-RGB-50X50]
D13  B5817  [D-0805]
FB11  FB_0603  [L-0603]
FB13  FB_0603  [L-0603]
R74  1K  [R-0603]
R75  47K  [R-0603]
R76  1K  [R-0603]
R77  1K  [R-0603]
R78  22  [R-0603]
R79  1K  [R-0603]
R80  22  [R-0603]
R81  22  [R-0603]
R82  22  [R-0603]
R83  22  [R-0603]
R84  0  [R-0603]
R85  22  [R-0603]
R86  22  [R-0603]
R87  22  [R-0603]
R88  22  [R-0603]
R89  22  [R-0603]
R90  22  [R-0603]
R91  22  [R-0603]
R92  1K  [R-0603]
R93  1K  [R-0603]
R94  22  [R-0603]
R95  1K  [R-0603]
R96  22  [R-0603]
R97  22  [R-0603]
R98  22  [R-0603]
R99  0  [R-0603]
R100  1K  [R-0603]
R101  1K  [R-0603]
R102  1K  [R-0603]
R103  22  [R-0603]
R104  22  [R-0603]
SW17  SW_DIP-4  [SW-DIP4]
U4  EN25T80-DIP  [DIP8-P2.54-W7.62]
U5  MX25LXX-SOP  [SOP8-P1.27-W6.2+8.1]
sheet 06. Keys
C42  0.1uF  [C-0603]
C43  0.1uF  [C-0603]
C44  0.1uF  [C-0603]
C45  0.1uF  [C-0603]
C46  0.1uF  [C-0603]
C47  0.1uF  [C-0603]
C48  0.1uF  [C-0603]
C49  0.1uF  [C-0603]
C50  0.1uF  [C-0603]
C51  0.1uF  [C-0603]
C52  0.1uF  [C-0603]
C53  0.1uF  [C-0603]
R105  2.2K  [R-0603]
R106  0  [R-0603]
R107  270  [R-0603]
R108  360  [R-0603]
R109  470  [R-0603]
R110  680  [R-0603]
R111  1K  [R-0603]
R112  1.8K  [R-0603]
R113  3.3K  [R-0603]
R114  12K  [R-0603]
R115  2.2K  [R-0603]
R116  2.2K  [R-0603]
R117  22  [R-0603]
R118  2.2K  [R-0603]
R119  2.2K  [R-0603]
R120  22  [R-0603]
R121  4.7K  [R-0603]
R122  12K  [R-0603]
R123  10  [R-0603]
SW4  SW1_4P  [SW-TACT-P4.5X6.5-Z6.2X6.2X5]
SW5  SW1_4P  [SW-TACT-P4.5X6.5-Z6.2X6.2X5]
SW6  SW1_4P  [SW-TACT-P4.5X6.5-Z6.2X6.2X5]
SW7  SW1_4P  [SW-TACT-P4.5X6.5-Z6.2X6.2X5]
SW8  SW1_4P  [SW-TACT-P4.5X6.5-Z6.2X6.2X5]
SW9  SW1_4P  [SW-TACT-P4.5X6.5-Z6.2X6.2X5]
SW10  SW1_4P  [SW-TACT-P4.5X6.5-Z6.2X6.2X5]
SW11  SW1_4P  [SW-TACT-P4.5X6.5-Z6.2X6.2X5]
SW12  SW1_4P  [SW-TACT-P4.5X6.5-Z6.2X6.2X5]
SW13  EC11_SW  [SW5P_EC11]
SW14  SW1_4P  [SW-TACT-P4.5X6.5-Z6.2X6.2X5]
SW15  SW1_4P  [SW-TACT-P4.5X6.5-Z6.2X6.2X5]
SW16  SW1_4P  [SW-TACT-P4.5X6.5-Z6.2X6.2X5]

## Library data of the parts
_DC_+5V1 _DC_GND1 = TPH-GND: Assembly: NC
C1 = CAP-NP_4: 2ND PART FIELD: SMD_0805; Package: 0603 Multilayer Ceramic Chip Capacitor
C2 C36 = CAP-POL_2: Package: 1008 Multilayer Ceramic Chip Capacitor
C3 C42 = CAP-NP_1: 2ND PART FIELD: SMD_0805; Package: 0603 Multilayer Ceramic Chip Capacitor
C4 = CAP-POL_5
C5 C15 C28 = CAP-NP_3
C6 C37 = CAP-POL: Package: 1008 Multilayer Ceramic Chip Capacitor
C7 = CAP-NP: 2ND PART FIELD: SMD_0805; Assembly: NC; Package: 0603 Multilayer Ceramic Chip Capacitor
C8 C21 = CAP-POL_4
C9 C20 C38 C54 = CAP-NP_2
C10 = CAP-POL_3: Package: 1008 Multilayer Ceramic Chip Capacitor
C11 C35 = CAP-POL_1: Package: 1008 Multilayer Ceramic Chip Capacitor
C12 = CAP-NP_5: 2ND PART FIELD: SMD_0805; Package: 0603 Multilayer Ceramic Chip Capacitor
CJ1 = CJ-DC-JACK-3P: 2ND PART FIELD: +12V DC Input; Function: +7V ~ +12V DC Input; Package: JACK3P-POWER
CJ2 = CJ-USB-AB: Assembly: NC; Package: USB_AB-Type
CJ3 = CJ-USB-Micro: Package: USB_Micro
D1 = LED: Assembly: Green; Function: +5V; Package: Red
D2 = LED: Assembly: Yellow; Function: +12V; Package: Yellow
D3 = LED: Assembly: Red; Function: +VDD; Package: Red
D4 = LED: Assembly: NC; Function: +5V_USB; Package: Red
D5 D13 = DIODE-SCHOTTKY-2: Assembly: NC; Function: SCHOTTKY DIODE; Package: D0805
D6 = DIODE-SCHOTTKY-2: Function: SCHOTTKY DIODE; Package: D0805
F1 = FUSE: 1ST PART FIELD: +12V 3A; Function: +12V 2A
FB1 FB6 = FB+DIP
FB2 FB15 = FB2_1: Assembly: NC
FB3 FB4 FB10 = FB2
G1-G4 = ScrewPad-9P: Assembly: NC
G5 = LOGO-Megawin_3_4: Assembly: NC
R1 R60 R100 = R_7: 2ND PART FIELD: SMD_0805; Package: 0603 SMD Resister
R2 R43 R68 = R_4: 2ND PART FIELD: SMD_0805; Package: 0603 SMD Resister
R3 = R: 2ND PART FIELD: SMD_0805; Package: 0603 SMD Resister
R4 R19 R93 = R_5: 2ND PART FIELD: SMD_0805; Assembly: NC; Package: 0603 SMD Resister
R5 R72 R124 = R_3: 2ND PART FIELD: SMD_0805; Package: 0603 SMD Resister
R6 = R_8
R7 R12 R41 = R_2: 2ND PART FIELD: SMD_0805; Package: 0603 SMD Resister
R8 = R_1
R9 = R_6
R10 = R_9
SW1 = SW-PB-6P
TC1 = CAP-EC_2: Package: 1210 Multilayer Ceramic Chip Capacitor
TC2 = CAP-EC_1: Package: 1210 Multilayer Ceramic Chip Capacitor
TC3 = CAP-EC: Package: 1210 Multilayer Ceramic Chip Capacitor
TP1-TP6 = TPH-GND: Assembly: NC; Package: Gold Test Pin
UP1 = ICP-AP1115B: Alternate: AIC1734-33,AP1115B-33; Function: +3.3V Regulator; Package: SOT-89
UP2 = ICP-AP1117: Function: +5V Regulator; Package: SOT-223
UP3 = ICP-AP1117: Function: +3.3V Regulator; Package: SOT-223
Z1 = DIODE-ZENER: Package: SMA(3x4.6mm)
_ICKO1 = TPH60-COIL: Assembly: NC
C13 = CAP-POL_2
C14 C29 = CAP-NP_1
C16 = CAP-POL_1
C17 = CAP-NP_4: Assembly: NC; Package: 0603 Multilayer Ceramic Chip Capacitor
C18 = CAP-NP_6: Assembly: NC; Package: 0603 Multilayer Ceramic Chip Capacitor
C19 = CAP-POL_3
C22 C27 = CAP-NP_5
C23 = CAP-POL
C24 = CAP-NP_7
C25 C30 = CAP-NP
CN1 = SIP6: Function: SWD Connector; Package: SIP6-2.54/Femail
FB5 FB9 FB11 = FB2_1
R11 R59 R126 = R_11: 2ND PART FIELD: SMD_0805; Package: 0603 SMD Resister
R13 R50 R63 = R_9: 2ND PART FIELD: SMD_0805; Package: 0603 SMD Resister
R14 = R_13: Package: 0603 SMD Resister
R15 R64 = R_10: Package: 0603 SMD Resister
R16 R119 = R: Package: 0603 SMD Resister
R17 R85 = R_6: 2ND PART FIELD: SMD_0805; Assembly: NC; Package: 0603 SMD Resister
R18 = R_14: 2ND PART FIELD: SMD_0805; Assembly: NC; Package: 0603 SMD Resister
R20 R91 R129 = R_1: 2ND PART FIELD: SMD_0805; Package: 0603 SMD Resister
R21 R71 R99 = R_8: 2ND PART FIELD: SMD_0805; Package: 0603 SMD Resister
R22 = R_7: Assembly: NC; Package: 0603 SMD Resister
R23 = R_4: Assembly: NC; Package: 0603 SMD Resister
R125 = R_12: 2ND PART FIELD: SMD_0805; Package: 0603 SMD Resister
SW2 = SW-PB-4P: Function: Reset
U1 = IC-MG32F02U128-LQFP80
X1 = XTAL-G: Assembly: NC
C26 = CAP-POL_1: Package: 0805 Multilayer Ceramic Chip Capacitor
C31 = CAP-POL: Assembly: NC; Package: 0805 Multilayer Ceramic Chip Capacitor
C32 = CAP-NP_6: 2ND PART FIELD: SMD_0805
C33 = CAP-NP_4: Package: C0603
C34 = CAP-NP_7: Package: C0603
CN2 = SIP2-SPK: Function: Speaker Connector; Package: P2.54mm
CN3 = HEADER12: Function: MF Connector-1; Package: Pitch 2.54mm/Female
CN4 = HEADER3_2: 2ND PART FIELD: Pitch 2.54mm; Function: MF Connector-2; Package: Pitch 2.54mm/Female
CN5 = HEADER3_1: 2ND PART FIELD: Pitch 2.54mm; Function: MF Connector-3; Package: Pitch 2.54mm/Female
CN6 = HEADER8: Function: I2C-1 Connector; Package: Pitch 2.54mm/Female
CN7 = HEADER4: Function: I2C-2 Connector; Package: Pitch 2.54mm/Female
CN15 = HEADER4X2: Function: BLE Interface; Package: HEADER4X2-2.54-Female
CN17 = HEADER3_4: 2ND PART FIELD: Pitch 2.54mm; Assembly: NC; Function: ARGB-URT CON; Package: Pitch 2.54mm/Female
EC1 = CAP_+_2: Package: CAP-CHIP/EC4
FB7 = FB2_4
FB8 = FB2_3
FB12 = FB2_2
FB13 FB14 = FB2: Assembly: NC
JP1 = HEADER3_3: 2ND PART FIELD: Pitch 2.54mm; Function: +VDD_I2C Select; Package: Pitch 2.54mm/Male
JP2 = HEADER3: 2ND PART FIELD: Pitch 2.54mm; Function: +VDD_MX Select; Package: Pitch 2.54mm/Male
R24 = R_21: Assembly: NC
R25 = R_41
R26 = R_42: 2ND PART FIELD: SMD_1
R27 = R_18: 2ND PART FIELD: SMD_1
R28 = R_23: Assembly: NC
R29 = R_38
R30 = R_5: 2ND PART FIELD: SMD_1; Assembly: NC
R31 = R_14
R32 = R_20: Assembly: NC
R33 = R_33: 2ND PART FIELD: SMD_0805; Package: 0603 SMD Resister
R34 R88 = R_10: 2ND PART FIELD: SMD_0805; Package: 0603 SMD Resister
R35 = R_30: 2ND PART FIELD: SMD_0805; Package: 0603 SMD Resister
R36 R94 = R_15: 2ND PART FIELD: SMD_0805; Package: 0603 SMD Resister
R37 = R_31: 2ND PART FIELD: SMD_0805; Package: 0603 SMD Resister
R38 R62 = R_6: 2ND PART FIELD: SMD_0805; Package: 0603 SMD Resister
R39 R65 = R_13: 2ND PART FIELD: SMD_0805; Package: 0603 SMD Resister
R40 = R_19: 2ND PART FIELD: SMD_0805; Package: 0603 SMD Resister
R42 = R_29: 2ND PART FIELD: SMD_0805; Package: 0603 SMD Resister
R44 = R_28: 2ND PART FIELD: SMD_0805
R45 = R_3: 2ND PART FIELD: SMD_0805
R46 = R_27: 2ND PART FIELD: SMD_0805; Assembly: NC; Package: 0603 SMD Resister
R47 R97 = R: 2ND PART FIELD: SMD_0805; Assembly: NC; Package: 0603 SMD Resister
R48 = R_26: 2ND PART FIELD: SMD_0805; Assembly: NC; Package: 0603 SMD Resister
R49 = R_35: 2ND PART FIELD: SMD_0805; Package: 0603 SMD Resister
R51 R90 = R_17: 2ND PART FIELD: SMD_0805; Package: 0603 SMD Resister
R52 = R_32: 2ND PART FIELD: SMD_0805; Assembly: NC; Package: 0603 SMD Resister
R53 R81 = R_12: 2ND PART FIELD: SMD_0805; Assembly: NC; Package: 0603 SMD Resister
R54 = R_36: 2ND PART FIELD: SMD_0805; Assembly: NC; Package: 0603 SMD Resister
R55 = R_7: 2ND PART FIELD: SMD_0805; Assembly: NC; Package: 0603 SMD Resister
R56 = R_24: 2ND PART FIELD: SMD_0805; Assembly: NC; Package: 0603 SMD Resister
R57 = R_39: 2ND PART FIELD: SMD_0805; Assembly: NC; Package: 0603 SMD Resister
R58 = R_8: 2ND PART FIELD: SMD_0805; Assembly: NC; Package: 0603 SMD Resister
R127 = R_16: 2ND PART FIELD: SMD_0805; Package: 0603 SMD Resister
R128 = R_25: 2ND PART FIELD: SMD_0805; Package: 0603 SMD Resister
R130 = R_34: 2ND PART FIELD: SMD_0805; Package: 0603 SMD Resister
R131 = R_37: 2ND PART FIELD: SMD_0805; Package: 0603 SMD Resister
R132 = R_22: 2ND PART FIELD: SMD_0805; Assembly: NC; Package: 0603 SMD Resister
R133 = R_40: 2ND PART FIELD: SMD_0805; Assembly: NC; Package: 0603 SMD Resister
TC4 = CAP_+: Assembly: NC
TC5 = CAP_+_1
U2 = IC-LM386: Function: Audio Amplifier
U3 = ICM-24CXX: 1ST PART FIELD: OSD Record Buffer; 2ND PART FIELD: SOP_8PIN; Function: I2C EEPROM
CN8 = HEADER20X2A: Function: LCD Module IF
CN9 = HEADER17X2: Function: LCD Interface-2
CN10 = HEADER14: Function: SPI LCD Interface-1
CN11 = HEADER11: Assembly: NC; Function: SPI LCD Interface-2
JP3 = HEADER3: 2ND PART FIELD: Pitch 2.54mm; Package: SIP 2.54mm
JP4 = JUMPER: Assembly: NC; Package: SIP2-RES
Q1 = TRN-NPN-2N3904: Assembly: NC
Q2 = MOS-N-SOT23: Assembly: NC
R61 R83 = R_14: 2ND PART FIELD: SMD_0805; Package: 0603 SMD Resister
R66 = R_5: 2ND PART FIELD: SMD_0805; Package: 0603 SMD Resister
R67 = R_12: Assembly: NC; Package: 0603 SMD Resister
R69 = R_1: 2ND PART FIELD: SMD_0805; Assembly: NC; Package: 0603 SMD Resister
R70 = R: Assembly: NC; Package: 0603 SMD Resister
R73 = R_2: Package: 0603 SMD Resister
RP1-RP4 = RP4-SMD2
C39 = CAP-NP_3: Package: 0603 Multilayer Ceramic Chip Capacitor
C40 = CAP-NP: Package: 0603 Multilayer Ceramic Chip Capacitor
C41 = CAP-NP_1: Package: 0603 Multilayer Ceramic Chip Capacitor
C55 = CAP-NP_4: Assembly: NC
CN12 = HEADER10: Function: SPI-1  Connector; Package: Pitch 2.54mm/Female
CN13 = HEADER6: Function: SPI-2  Connector; Package: Pitch 2.54mm/Female
CN14 = SIP4: Package: SIP4-2.54
CN16 = HEADER4X2: Assembly: NC; Function: BLE Interface; Package: HEADER4X2-2.54-Female
D7 D8 = LED: ATHEROS KEY: 127-00026-000; AtherosDescription: LED, THRU_HOLE,GREEN,3.0MM RADIAL; CISPartType: Diodes\LED
D9 D10 = LED: ATHEROS KEY: 127-00026-000; Assembly: NC; AtherosDescription: LED, THRU_HOLE,GREEN,3.0MM RADIAL; CISPartType: Diodes\LED
D11 = LED-6P-RGB: Assembly: NC; Function: RGB LED; Package: GTG5050RGBC
D12 = LED-6P-RGB: Function: RGB LED; Package: GTG5050RGBC
R74 R76 = R2X
R75 = R_13: Package: R0603
R77 R79 = R2X: Assembly: NC
R78 = R_25: 2ND PART FIELD: SMD_0805; Assembly: NC; Package: 0603 SMD Resister
R80 = R_3: 2ND PART FIELD: SMD_0805; Assembly: NC; Package: 0603 SMD Resister
R82 = R_19: 2ND PART FIELD: SMD_0805; Assembly: NC; Package: 0603 SMD Resister
R84 = R_4: 2ND PART FIELD: SMD_0805; Assembly: NC; Package: 0603 SMD Resister
R86 = R_26: 2ND PART FIELD: SMD_0805; Package: 0603 SMD Resister
R87 = R_2: 2ND PART FIELD: SMD_0805; Assembly: NC; Package: 0603 SMD Resister
R89 = R_16: 2ND PART FIELD: SMD_0805; Assembly: NC; Package: 0603 SMD Resister
R92 = R_18: 2ND PART FIELD: SMD_0805; Assembly: NC; Package: 0603 SMD Resister
R95 = R_20: 2ND PART FIELD: SMD_0805; Assembly: NC; Package: 0603 SMD Resister
R96 = R_21: 2ND PART FIELD: SMD_0805; Assembly: NC; Package: 0603 SMD Resister
R98 = R_9: 2ND PART FIELD: SMD_0805; Assembly: NC; Package: 0603 SMD Resister
R101 = R_23: 2ND PART FIELD: SMD_0805; Package: 0603 SMD Resister
R102 = R_22: 2ND PART FIELD: SMD_0805; Package: 0603 SMD Resister
R103 = R_24: Package: 0603 SMD Resister
R104 = R_11: Package: 0603 SMD Resister
SW17 = SW-DIP4: Assembly: NC
U4 = ICM-25FXX: Assembly: NC; Function: SPI Flash; Package: DIP8-2.54\300mil
U5 = ICM-25LXX: Function: SPI Flash
C43 = CAP_2: 2ND PART FIELD: SMD_0805; Assembly: NC
C44 = CAP_9: 2ND PART FIELD: SMD_0805; Assembly: NC
C45 = CAP_8: 2ND PART FIELD: SMD_0805; Assembly: NC
C46 = CAP_1: 2ND PART FIELD: SMD_0805; Assembly: NC
C47 = CAP_5: 2ND PART FIELD: SMD_0805; Assembly: NC
C48 = CAP: 2ND PART FIELD: SMD_0805; Assembly: NC
C49 = CAP_4: 2ND PART FIELD: SMD_0805; Assembly: NC
C50 = CAP_7: 2ND PART FIELD: SMD_0805; Assembly: NC
C51 = CAP-NP: 2ND PART FIELD: SMD_0805; Package: 0603 Multilayer Ceramic Chip Capacitor
C52 = CAP_3: 2ND PART FIELD: SMD_0805; Assembly: NC
C53 = CAP_6: 2ND PART FIELD: SMD_0805; Assembly: NC
R105 = R_4: 2ND PART FIELD: SMD_0805
R106 = R_17: Package: 0603 SMD Resister
R107 = R_14: 2ND PART FIELD: SMD_1
R108 = R_3: 2ND PART FIELD: SMD_1
R109 = R_2: 2ND PART FIELD: SMD_1
R110 = R_11: 2ND PART FIELD: SMD_1
R111 = R_13: 2ND PART FIELD: SMD_1
R112 = R_7: Package: 0603 SMD Resister
R113 = R_15: 2ND PART FIELD: SMD_1
R114 = R_8: 2ND PART FIELD: SMD_1
R115 = R_12: 2ND PART FIELD: SMD_0805
R116 = R_10: Assembly: NC
R117 = R_16: Assembly: NC
R118 = R_6: Assembly: NC
R120 = R_5: Assembly: NC
R121 = R_9: 2ND PART FIELD: SMD_1
R122 = R_1: 2ND PART FIELD: SMD_1
R123 = R_18: Assembly: NC
SW4 SW10 SW14 = SW-PB-4P: Function: Power KEY
SW5 SW11 SW15 = SW-PB-4P: Function: Return KEY
SW6 SW12 SW16 = SW-PB-4P: Function: + KEY
SW7 = SW-PB-4P: Function: Up KEY
SW8 = SW-PB-4P: Function: Down KEY
SW9 = SW-PB-4P: Function: - KEY
SW13 = SW-EC11: Assembly: NC

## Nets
+5V: C4.1 C5.1 C8.1 C9.1 C11.1 FB2.1 FB7.1 FB9.1 JP1.3 JP2.3 JP3.1 R1.1 R67.2 SW1.2 SW1.5 UP1.2(OUT) UP1.4(VOUT) UP3.3(IN) Z1.2(CATHODE)
+5V_IN: _DC_+5V1.1 D5.2(CATHODE) D6.2(CATHODE) FB1.2 R4.1 SW1.3 SW1.6 TC2.1
+5V_LDO: C2.1 FB1.1 R5.1 UP2.2(OUT) UP2.4(VOUT)
+5V_USB: C7.1 CJ2.1(USBA_PWR) CJ2.7(USBB_PWR) D5.1(ANODE)
+5V_USB2: C12.1 CJ3.1(USB_PWR) D6.1(ANODE)
+12V: C3.1 F1.2 FB14.1 FB15.1 R2.1 TC1.1 UP2.3(IN)
+12V_JC: C1.1 CJ1.1(CENTER) F1.1
+12V_MX: CN4.3 FB15.2
+V33_MG: C21.1 R17.1 U1.60(V33/PD6)
+VDD: CN17.1 D7.1(A) D8.1(A) D9.1(A) D10.1(A) D11.1 D11.3 D11.5 D12.1 D12.3 D12.5 D13.1(ANODE) FB2.2 FB3.2 FB4.1 FB5.2 FB6.2 FB8.1 FB11.2 FB12.2 FB13.2 JP1.1 JP2.1 R3.1 R105.1 R115.1 R116.2 R118.2 TC3.1
+VDD_AMP: C26.1 C27.1 FB7.2 FB14.2 U2.6(VS)
+VDD_BLE: C54.1 CN15.2 FB12.1
+VDD_BLE2: C55.1 CN16.2 FB13.1
+VDD_EP: C32.1 FB8.2 R44.1 R45.1 U3.8(VCC)
+VDD_FS: C38.1 CN13.2 FB11.1 R75.1 U4.8(VDD) U5.8(VDD)
+VDD_I2C: CN6.8 JP1.2
+VDD_LDO: C6.1 FB3.1 R6.1 UP1.3(IN)
+VDD_MG1: C15.1 C16.1 FB4.2 R11.2 U1.72(VDD)
+VDD_MG2: C23.1 C24.1 FB5.1 R15.2 U1.27(VDD2)
+VDD_MX: CN4.1 CN4.2 JP2.2
+VDD_SWD: C25.1 CN1.4 FB6.1 R22.2 R23.2
+VDD_UART0: C39.1 CN14.1 D13.2(CATHODE)
GND: _DC_GND1.1 C1.2 C2.2 C3.2 C4.2 C5.2 C6.2 C7.2 C8.2 C9.2 C10.2 C11.2 C12.2 C13.2 C14.2 C15.2 C16.2 C17.2 C18.2 C19.2 C20.2 C21.2 C22.2 C23.2 C24.2 C25.2 C26.2 C27.2 C30.2 C31.2 C32.2 C33.2 C34.2 C35.2 C36.2 C37.2 C38.2 C39.2 C40.2 C41.2 C42.2 C43.2 C44.2 C45.2 C46.2 C47.2 C48.2 C49.2 C50.2 C51.2 C54.2 C55.2 CJ1.2(SHIELD1) CJ1.3(SHIELD2) CJ2.4(USBA_GND) CJ2.5(shield_A0) CJ2.6(shield_A1) CJ2.10(USBB_GND) CJ2.11(shield_B0) CJ2.12(shield_B1) CJ3.4(USB_ID) CJ3.5(USB_GND) CJ3.6(shield_1) CJ3.7(shield_2) CJ3.8(shield_3) CJ3.9(shield_4) CN1.2 CN2.1(SPK-) CN5.1 CN5.2 CN5.3 CN6.4 CN8.1 CN9.8 CN9.9 CN9.13 CN10.2 CN11.1 CN13.6 CN14.2 CN15.1 CN16.1 CN17.3 D1.2(C) D2.2(C) D3.2(C) D4.2(C) G1.1 G1.2 G1.3 G1.4 G1.5 G1.6 G1.7 G1.8 G1.9 G2.1 G2.2 G2.3 G2.4 G2.5 G2.6 G2.7 G2.8 G2.9 G3.1 G3.2 G3.3 G3.4 G3.5 G3.6 G3.7 G3.8 G3.9 G4.1 G4.2 G4.3 G4.4 G4.5 G4.6 G4.7 G4.8 G4.9 JP4.2 Q1.2(E) R7.2 R8.2 R10.2 R28.2 R29.2 R31.2 R32.2 R119.1 R121.1 R122.1 SW2.2 SW4.2 SW4.4 SW5.2 SW5.4 SW6.2 SW6.4 SW7.2 SW7.4 SW8.2 SW8.4 SW9.2 SW9.4 SW10.2 SW10.4 SW11.2 SW11.4 SW12.2 SW12.4 SW13.2(Com) SW13.4(S2) SW17.1(A1) SW17.2(A2) SW17.3(A3) SW17.4(A4) TC1.2 TC2.2 TC3.2 TC5.2 TP1.1 TP2.1 TP3.1 TP4.1 TP5.1 TP6.1 U1.30(VSS2) U1.49(VSS1) U1.70(VSS) U2.2(IN-) U2.4(GND) U3.1(A0) U3.2(A1) U3.3(A2) U3.4(GND) U3.7(WP) U4.4(GND) U5.4(GND) X1.3 Z1.1(ANODE)
+LCD_5V: C35.1 CN8.18 CN9.7 FB9.2
+LCD_BL: C37.1 CN8.19 CN9.10 CN9.11 FB10.2 Q2.2(S) R69.1
+LCD_LDO: C10.1 FB10.1 JP3.3 Q2.3(D) R9.1 UP3.2(OUT) UP3.4(VOUT)
+LCD_VCC: C36.1 CN8.2 CN10.1 CN11.2 JP3.2 R64.2
ARGB_IO: CN17.2 R131.1 R132.1 R133.1
AU_OUT: C28.2 C31.1 R27.2 R28.1 R30.2
BL_CTL2: CN10.8 CN11.7 R66.2 R69.2
BL_IRQ: CN15.8 R130.1
BL_MISO: CN15.7 R127.1
BL_MOSI: CN15.6 R129.1
BL_NSS: CN15.4 R126.1
BL_SCK: CN15.5 R128.1
FLASH_AUX: CN13.3 CN16.8 R96.2
FLASH_CEN: CN12.6 R75.2 R83.2 R84.2 U4.1(CE#) U5.1(CE#)
FLASH_CEN2: CN13.1 CN16.4 R84.1 R85.2 R99.1
FLASH_D0: CN12.9 CN16.6 R91.2 U4.5(SI) U5.5(D0/SI)
FLASH_D1: CN12.5 CN16.7 R86.2 R87.2 U4.2(SO) U5.2(SO/D1)
FLASH_D2: CN12.7 R88.2 R89.2 U4.3(WP#) U5.3(WP/D2)
FLASH_D3: CN12.8 R90.2 U4.7(HOLD#) U5.7(D3/RST)
FLASH_D4: CN12.4 R82.2
FLASH_D5: CN12.1 R78.2
FLASH_D6: CN12.2 R80.2
FLASH_D7: CN12.3 R81.2
FLASH_DQS: CN13.4 R97.2
FLASH_RSTN: CN13.5 R98.2 R99.2
FLASH_SCK: CN12.10 CN16.5 R94.2 U4.6(SCK) U5.6(SCK)
I2C_A0: CN6.1 R52.1
I2C_A1: CN6.2 R53.1
I2C_A2: CN6.3 R54.1
I2C_AUX0: CN7.1 R55.1
I2C_AUX1: CN7.2 R56.1
I2C_AUX2: CN7.3 R57.1
I2C_AUX3: CN7.4 R58.1
I2C_SCL: C34.1 CN6.6 R45.2 R47.1 R49.1 U3.6(SCL)
I2C_SDA: C33.1 CN6.5 R44.2 R48.1 R50.1 U3.5(SDA)
I2C_WP: CN6.7 R51.1
KEY0: R105.2 R106.2 R107.1 SW4.1 SW4.3
KEY1: C43.1 R107.2 R108.1 SW5.1 SW5.3
KEY2: C44.1 R108.2 R109.1 SW6.1 SW6.3
KEY3: C45.1 R109.2 R110.1 SW7.1 SW7.3
KEY4: C46.1 R110.2 R111.1 SW8.1 SW8.3
KEY5: C47.1 R111.2 R112.1 SW9.1 SW9.3
KEY6: C48.1 R112.2 R113.1 SW10.1 SW10.3
KEY7: C49.1 R113.2 R114.1 SW11.1 SW11.3
KEY8: C50.1 R114.2 SW12.1 SW12.3
LCD_CS: CN8.15 CN9.34 R61.2
LCD_CS2: CN10.3 CN11.9 R72.2
LCD_DB0: CN8.14 CN9.29 RP4.5
LCD_DB1: CN8.13 CN9.28 RP4.6
LCD_DB2: CN8.12 CN9.27 RP4.7
LCD_DB3: CN8.11 CN9.26 RP4.8
LCD_DB4: CN8.10 CN9.25 RP3.5
LCD_DB5: CN8.9 CN9.24 RP3.6
LCD_DB6: CN8.8 CN9.23 RP3.7
LCD_DB7: CN8.7 CN9.22 RP3.8
LCD_DB8: CN8.28 CN9.21 RP2.5
LCD_DB9: CN8.27 CN9.20 RP2.6
LCD_DB10: CN8.26 CN9.19 RP2.7
LCD_DB11: CN8.25 CN9.18 RP2.8
LCD_DB12: CN8.24 CN9.17 RP1.5
LCD_DB13: CN8.23 CN9.16 RP1.6
LCD_DB14: CN8.22 CN9.15 RP1.7
LCD_DB15: CN8.21 CN9.14 RP1.8
LCD_RD: CN8.6 CN9.31 R63.2
LCD_RS: CN8.4 CN9.33 CN10.5 CN11.6 R60.2
LCD_RSTN: CN8.17 CN9.30 CN10.4 CN11.5 JP4.1 R59.2 R64.1
LCD_SCK: CN10.7 CN11.3 R71.2
LCD_SDI: CN10.6 CN11.4 R65.2
LCD_SDO: CN10.9 CN11.8 R68.2
LCD_WR: CN8.5 CN9.32 R62.2
MG_DM: CJ3.2(USB_DM) R13.2
MG_DP: CJ3.3(USB_DP) R12.2
MG_PA0: R55.2 R100.2 U1.74(ADC0/PA0)
MG_PA1: R56.2 R101.2 U1.75(ADC1/PA1)
MG_PA2: R57.2 R102.2 U1.76(ADC2/PA2)
MG_PA3: R58.2 U1.77(ADC3/PA3)
MG_PA4: R65.1 U1.78(ADC4/PA4)
MG_PA5: R68.1 U1.79(ADC5/PA5)
MG_PA6: R71.1 U1.80(ADC6/PA6)
MG_PA7: R72.1 U1.1(PA7/ADC7)
MG_PA8: R41.2 U1.2(PA8/ADC8)
MG_PA9: R40.2 U1.3(PA9/ADC9)
MG_PA10: R30.1 R43.2 R130.2 U1.4(PA10/ADC10)
MG_PA11: R42.2 R131.2 U1.5(PA11/ADC11)
MG_PA12: R39.2 R117.2 U1.6(PA12/ADC12)
MG_PA13: R38.2 R120.2 U1.7(PA13/ADC13)
MG_PA14: C51.1 C52.1 C53.1 R37.2 R115.2 R123.2 SW14.1 SW14.3 SW15.1 SW15.3 SW16.1 SW16.3 U1.8(PA14/ADC14)
MG_PA15: C42.1 R46.2 R106.1 U1.9(PA15/ADC15)
MG_PB0: R33.2 R47.2 R126.2 U1.10(PB0/NSS)
MG_PB1: R34.2 R48.2 R128.2 U1.11(PB1/MISO)
MG_PB2: R27.1 R35.2 U1.12(PB2/SCK)
MG_PB3: R36.2 R129.2 R132.2 U1.13(PB3/MOSI)
MG_PB4: R59.1 U1.18(PB4/SD3)
MG_PB5: R63.1 U1.19(PB5/SD2)
MG_PB6: R62.1 U1.20(PB6)
MG_PB7: R61.1 U1.21(PB7)
MG_PB8: RP4.4 U1.22(PB8/TXD0)
MG_PB9: RP4.3 U1.23(PB9/RXD0)
MG_PB10: RP4.2 U1.24(PB10/SCL0)
MG_PB11: RP4.1 U1.25(PB11/SDA0)
MG_PB12: RP3.4 U1.26(PB12)
MG_PB13: RP3.3 U1.28(PB13)
MG_PB14: RP3.2 U1.29(PB14)
MG_PB15: RP3.1 U1.31(PB15)
MG_PC0: _ICKO1.1 U1.34(PC0/ICKO)
MG_PC1: RP2.4 U1.35(PC1)
MG_PC2: RP2.3 U1.36(PC2)
MG_PC3: RP2.2 U1.37(PC3)
MG_PC4: R20.1 U1.38(PC4/SWCLK)
MG_PC5: R21.1 U1.39(PC5/SWDIO)
MG_PC6: C22.1 R15.1 R16.1 U1.40(PC6/RSTN)
MG_PC7: R60.1 U1.41(PC7)
MG_PC8: RP2.1 U1.42(TXD1/PC8)
MG_PC9: RP1.4 U1.43(RXD1/PC9)
MG_PC10: RP1.3 U1.44(SCL1/PC10)
MG_PC11: RP1.2 U1.45(SDA1/PC11)
MG_PC12: RP1.1 U1.46(PC12)
MG_PC13: R74.2 R125.2
MG_PC14: R76.2 R124.2
MG_PD0: R83.1 U1.54(PD0)
MG_PD1: R94.1 U1.55(PD1)
MG_PD2: R91.1 U1.56(PD2)
MG_PD3: R90.1 U1.57(PD3)
MG_PD4: R19.2 R89.1
MG_PD4x: R13.1 R19.1 U1.58(DM/PD4)
MG_PD5: R18.2 R87.1
MG_PD5x: R12.1 R18.1 U1.59(DP/PD5)
MG_PD6: R17.2 R85.1
MG_PD7: R82.1 R86.1 U1.61(PD7)
MG_PD8: R81.1 R88.1 U1.62(PD8)
MG_PD9: R80.1 U1.63(PD9)
MG_PD10: R78.1 U1.64(PD10)
MG_PD11: R92.2 R96.1 U1.65(PD11)
MG_PD12: R93.2 R97.1 U1.66(CMP0/PD12)
MG_PD13: R52.2 R95.2 R98.1 U1.67(CMP1/PD13)
MG_PD14: R53.2 U1.68(PD14)
MG_PD15: R54.2 U1.69(PD15)
MG_PE0: R104.2 U1.14(PE0/OBMI0)
MG_PE1: R51.2 R103.2 U1.15(PE1/OBMI1)
MG_PE2: R49.2 U1.16(PE2)
MG_PE3: R50.2 R133.2 U1.17(PE3/OBMP1)
MG_PE8: R127.2 U1.32(PE8)
MG_PE9: CN9.12 R66.1 R70.1 R73.1 U1.33(PE9)
MG_PE12: SW17.8(B1) U1.50(PE12)
MG_PE13: SW17.7(B2) U1.51(PE13)
MG_PE14: R77.2 SW17.6(B3) U1.52(PE14)
MG_PE15: R79.2 SW17.5(B4) U1.53(PE15)
MG_VR0X: C19.1 C20.1 U1.71(VR0)
MG_VREFX: C13.1 C14.1 R11.1 U1.73(VREF+)
MX_G0: CN3.1 R37.1
MX_G1: CN3.2 R38.1
MX_G2: CN3.3 R39.1
MX_G3: CN3.4 R40.1
MX_G4: CN3.5 R41.1
MX_G6: CN3.7 R42.1
MX_G7: CN3.8 R43.1
MX_G11: CN3.12 R46.1
MX_MISO: CN3.9 R34.1
MX_NSS: CN3.6 R33.1
MX_RXD: CN3.11 R36.1
MX_TXD: CN3.10 R35.1
RST_CHIP: R14.2 R16.2 SW2.1
SK_A: R116.1 R117.1 SW13.1(A)
SK_B: R118.1 R120.1 SW13.3(B)
SK_SW: R123.1 SW13.5(S1)
SWCLK: CN1.5 R20.2 R23.1
SWDIO: CN1.3 R21.2 R22.1
SWSRST: CN1.1 R14.1
TS_LED0: D7.2(C) R74.1
TS_LED1: D8.2(C) R76.1
TS_LED2: D9.2(C) R77.1
TS_LED3: D10.2(C) R79.1
U5V0_RXD: C41.1 CN14.3 R103.1
U5V0_TXD: C40.1 CN14.4 R104.1
XIN: C17.1 R125.1 U1.47(XIN/PC13) X1.2
XOUT: C18.1 R124.1 U1.48(XOUT/PC14) X1.1
N45908496: R5.2 R7.1 UP2.1(ADJ)
N65646287: R9.2 R10.1 UP3.1(ADJ)
N65855464: Q1.3(C) Q2.1(G) R67.1 R73.2
N66229482: R6.2 R8.1 UP1.1(ADJ)
N66276767: R119.2 SW14.2 SW14.4
N66276834: C52.2 R121.2 SW15.2 SW15.4
N66276838: C53.2 R122.2 SW16.2 SW16.4
N66338352: Q1.1(B) R70.2
N66465989: R24.1 U2.1(GAIN1)
N66465991: TC4.2 U2.8(GAIN2)
N66466052: C28.1 R25.1
N66466067: R25.2 R29.1 U2.3(IN+)
N66466083: C29.1 EC1.1 U2.5(VOUT)
N66466128: TC5.1 U2.7(BYPASS)
N66466147: EC1.2 R26.1 R32.1
N66466196: C30.1 CN2.2(SPK+) R26.2
N66466238: R24.2 TC4.1
N66681787: D11.6 R95.1
N66681788: D11.2 R92.1
N66681791: D12.6 R102.1
N66681792: D12.4 R101.1
N66681793: D12.2 R100.1
N66681794: D11.4 R93.1
N66697892: D1.1(A) R1.2
N66697894: D4.1(A) R4.2
N66697895: D2.1(A) R2.2
N66697896: D3.1(A) R3.2
N66712506: C29.2 R31.1

Not connected (* = marked no-connect by the designer): CJ2 2(USBA_DM)* 3(USBA_DP)* 8(USBB_DM)* 9(USBB_DP)*; CN1 6*; CN8 3* 16* 20* 29* 30* 31* 32* 33* 34* 35* 36* 37* 38* 39* 40*; CN9 1* 2* 3* 4* 5* 6*; CN10 10* 11* 12* 13* 14*; CN11 10* 11*; CN15 3*; CN16 3*; G5 1(.); SW1 1* 4*; SW2 3* 4*

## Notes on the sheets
sheet 1
- MG04-04A
- 2021.05
- GR08-2105B
- MG32F02U USB+LCD DMB
- *Short these ground planes on PCB
- PCB Screw Position
- Power Jack DC 7~12V In
- System Power (5V)
- Chip IO Power (3.3V)
- If use AP1085-5 then:
- Ra= NC & Rb = 0
- +5V about 5.17 volt
- +5V_LDO=1.25*(1+Rb/Ra)
- +VDD_LDO=1.25*(1+Rb/Ra)
- +VDD_LDO about 3.33 volt
- Ra
- Ra
- Rb
- Rb
- If use AP1115B-33 then:  Ra= NC & Rb = 0
- USB Connector
- Extra DC Power Con
- LCD Power (3.3V)
- +LCD_LDO=1.25*(1+Rb/Ra)
- +LCD_LCD about 3.33 volt
- Ra
- Rb
- VDD Power
sheet 2
- Xtal
- Close to chip
- Chip Reset
- close chip
- Close to chip
- SWD
- Can use B5817
  SCHOTTKY DIODE
- SWOUT
- Test Clock Output
sheet 3
- Audio Speaker Out
- DAC_P0
- TM36_OC2H
- TC5 is optional for
  Power Supply Rejection
- Gain =20 : R24/TC4 NC
  Gain =50 : R24/TC4 On
- NSS
- MISO
- SCK
- Multi-Function Connector
- UART
- I2C
- SPI
- MISO
- NSS
- RXD
- TXD
- SCL
- SDA
- MISO
- NSS
- TM00_CKO
- TM16_TRGO
- MOSI
- SDA/SCK
- TXD
- SDA
- SCK
- DAC_P0
- RX
- SCL/MOSI
- RXD
- SCL
- MOSI
- TM26_OC1H
- GPIO
- TX
- SD3
- TM36_IC0
- TM36_IC1
- BLE Connector-1
- SD2
- SD1
- SDA/SCK
- SCL/MOSI
- (CT)
- (SCK)
- (CSN)
- (MOSI)
- (MISO)
- (IRQ)
- I2C Module (IR TX/RX)
- SCL
- TXD
- SDA
- RXD
- EEPROM
- SCL
- TXD
- SDA
- RXD
- IR_RX
- IR_TX
- (IR_RX)
- IR_RX
- TM20_IC0
- IR_TX
- IR_OUT
- (IR_TX)
- LED_B0
- TM36_OC00
- LED_G0
- LED_R0
- TM36_OC10
- TM36_OC2
- ARGB
  Connector
- (PB3) MOSI/URT0_RX/URT1_TX
sheet 4
- 8080 LCD Module-1
- 8080 LCD Module-2
- SPI LCD Module-1
- DB0
- TP_SCK
- CT_SCL
- TP_CS
- VCC
- DB1
- BUSY
- TP_WR
- GND
- DB2
- TP_SI
- CT_SDA
- TP_SO
- PA7
- CS
- (D/C)
- DB3
- (+5V)
- PB4
- RST
- (WR)
- DB4
- (+3V3)
- PC7
- D/C
- (RD)
- DB8
- DB5
- DB6
- (+3V3)
- (H=On)
- PA4
- PA6
- SCK
- SDI
- DB9
- DB7
- LED
- LCD Common IF
- DB10
- TCLK
- PA5
- SDO
- DB11
- TCS
- T_CLK
- DB12
- TDIN
- T_CS
- DB13
- DB14
- TDO
- T_DIN
- T_DOUT
- DB15
- TIRQ
- T_IRQ
- (CS)
- SD_DO
- 8080 LCD IF
- F_CS
- SD_CLK
- (RD)
- (WR)
- SD_DIN
- (D/C)
- (CS)
- SD_CS
- SPI 2.2TFT-ILI9341 (240x320)
- 4.3TFTLCD (480x800)(ALIENTEK-NT35510)
- SPI LCD Module-2
- 3.2TFT-ILI9341 (240x320)(TFT-320QVT-9341)
  2.4TFT-ILI9325 (240x320)
- GND
- VCC
- PA6
- SCK
- LCD Power
- LCD Reset
- PA4
- MOSI
- PB4
- RST
- (3.3V/5V)
- PC7
- D/C
- LED
- PA5
- MISO
- PA7
- CS
- T_CS
- T_IRQ
- 1-2 : +5V
  2-3 : +LCD_LDO
- Place RP9~12 on Bottom Side
- Swap MG_xx and LCD_DBxx Lsb/Msb nets
  if place on Top Side
- 8080 LCD Backlight Control
- SPI LCD Backlight Control
- SPI LCD IF
- FBd
- (2.9V~3.5V)
- Rc
- If use Q1, R73=NC.
- If use Q2, FBd=NC.
sheet 5
- SPI Connector
- SPI Flash
- RGB LED Display
- RGB-0
- RGB-1
- (MISO)
- LED Display
- (MOSI)
- Optional Part
- LED0
- LED1
- UART Connector-0
- LED2
- LED3
- (Input)
- CFG Setting
- (Output)
- These parts close to CN14
- BLE Connector-2
- (CT)
- (CSN)
- (SCK)
- (MOSI)
- (MISO)
- (IRQ)
sheet 6
- <+3V3>
- Key Board (SARADC)
- <0v>
- <0.36v>
- <0.73v>
- <1.10v>
- <1.48v>
- <1.84v>
- KEY2
- KEY1
- KEY0
- KEY5
- KEY4
- KEY3
- KEY8
- KEY7
- KEY6
- Shuttle Key
- KEY12
- KEY11
- KEY10
- PCB Position
- <2.23v>
- <2.58v>
- <2.96v>
- <+3V3>
- [Composited Key]
  Key10+Key11 : 1.34v
  Key10+Key12 : 1.51v
  Key11+Key12 : 2.00v
  [Shuttle Key]
  SW : 0v
- TM36_IC0
- TM36_IC1
- <1.65v>
- <2.25v>
- <2.79v>
sheet 7
- Board Features :
- Layout Rule :
- * MG32F02U Demo Board
- * Impedance :
- * USB Device Interface
- 1. Single-end signals ~ 12 mil/124ohm(Coated MicroStrip) for general nets
  2. Single-end signals ~ 10 mil/129ohm(Coated MicroStrip) for LQFP80
  3. Single-end signals with ground shield ~ 12-6/61ohm(Coated Coplanar Strips)
  4. USB differential signals ~ 15-5-15/90ohm (Edge-Coupled Coated MicroStrip)
- * 8/16-bit 8080 LCD Interface
- * SPI LCD Interface
- * Multi-Function Module Interface
- * I2C Module Interface
- * Power/Ground :
- * SPI Flash Module Interface
- 1. Bypass cap. need close to related power/ground pin
- * BLE Module Interface
- 2. Using Copper for DC input source and LDO input/output path
- * RGB LED
- * Clock/XTAL :
- * SARADC/Shuttle Key Input
- 1. Ground shielding and arc routing
- * Mono Audio Out
- 2. Signal trace cross orthogonal with test point outline and do not directly pass
  through  the central hole of test point for high speed signal
- Power ~
- * 12V DC Jack , 5V DC SIP2-2.54 , USB-A/B/Micro Connector
- Board Note :
- * Built-in 12V-to-5V LDO Circuit
- * Built-in 5V-to-3.3V(VDD) LDO Circuit
- * Ferrite Beed Spec :
- * Built-in 5V-to-3.3V(LCD) LDO Circuit
- FB :     Rdc=0.2 , Z=300/100MHz , Idc=500mA ~ MCB2012S301H
  FB_L : Rdc=0.015 , Z=120/100MHz , Idc=6000mA ~ MHC3216S121W
  FB_S : Rdc=0.25 , Z=60/100MHz , Idc=500mA ~ MCB1608H600H
  FB_0603 :     Rdc=0.15 , Z=120/100MHz , Idc=500mA ~ MCB1608S121H
- Debug Interface ~
- * SWD IF Connector SIP6-2.54 *1
- * UART Connector SIP4-2.54 * 2
- Module IF
- ECO List on Circuit:
- * 8080 LCD Module Connector 20x2 *1, 17x2 *1
- 1. Remove CJ2 MG_DP/MG_DM signals
- * SPI LCD Module Connector 14x1 *1, 11x1 *1
- 2. Change EC1 footprint from C-EC-S-P6.0_DIP to C-EC-S-P7.2-T6.3X5.5 and fix pad no mask error
- * Multi-Function Module Connector
- 3. Add CN17 ARGB connector
- * I2C Module Connector
- 4. Add FB14 and rename +5V_AMP to VDD_AMP
- * SPI Flash Module Connector
- 5. Add FB15 and change CN4 pin-3 net to +12V_MX
- * BLE Module Connector
- 6. Change BL_CTL net (R70/R73) from PE8 to PE9
- * ARGB Connector
- 7. Change R127/R128/R130/R30 net from PB1/PB2/PB3/PA9 to PE8/PB1/PA10/PA10
- On Board Component Circuit
- 8. Remove R131 ~ R135
- 9. Change CN17 net from MG_PB3 to ARGB_IO and add R131/R132/R133
- * SPI Flash DIP + SOP
- * LM386 Circuit  *1
- ECO List on PCB only:
- * EEPROM SOP *1
- 1. Correct CN12/CN13 placement on PCB
- * MCU XTAL Circuit  *1
- 2. Swap SW7(KEY3) and SW9(KEY5) placement on PCB
- Others ~
- 3. Change  SW13(shuttle Key) footprint to short the width of two ground pins
- * Trap DIP Switch 2x2 *1
- 4. Add one independent Outline-Line for SW14~SW16  on PCB
- 5. Change CJ3 footprint from USB5A-MICRO-290X220P065 to
- * RGB LED *2
- * User LED *4
- * Push Button  *1 (Reset )
- * SARADC Key Matrix  3x4
- * Shuttle Key Circuit  *1
sheet 8
- Module Board Dimension:
